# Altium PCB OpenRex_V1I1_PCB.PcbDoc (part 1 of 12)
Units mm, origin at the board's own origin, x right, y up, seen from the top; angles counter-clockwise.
Board outline 70 x 95 mm, 10 copper layers (L1, L2, L3, L4 (PWR), L5 (PWR), L6 (PWR), L7 (PWR), L8, L9, L10), stack 1.632 mm thick; 1080 components, 708 nets, 3831 pads, 2373 vias.
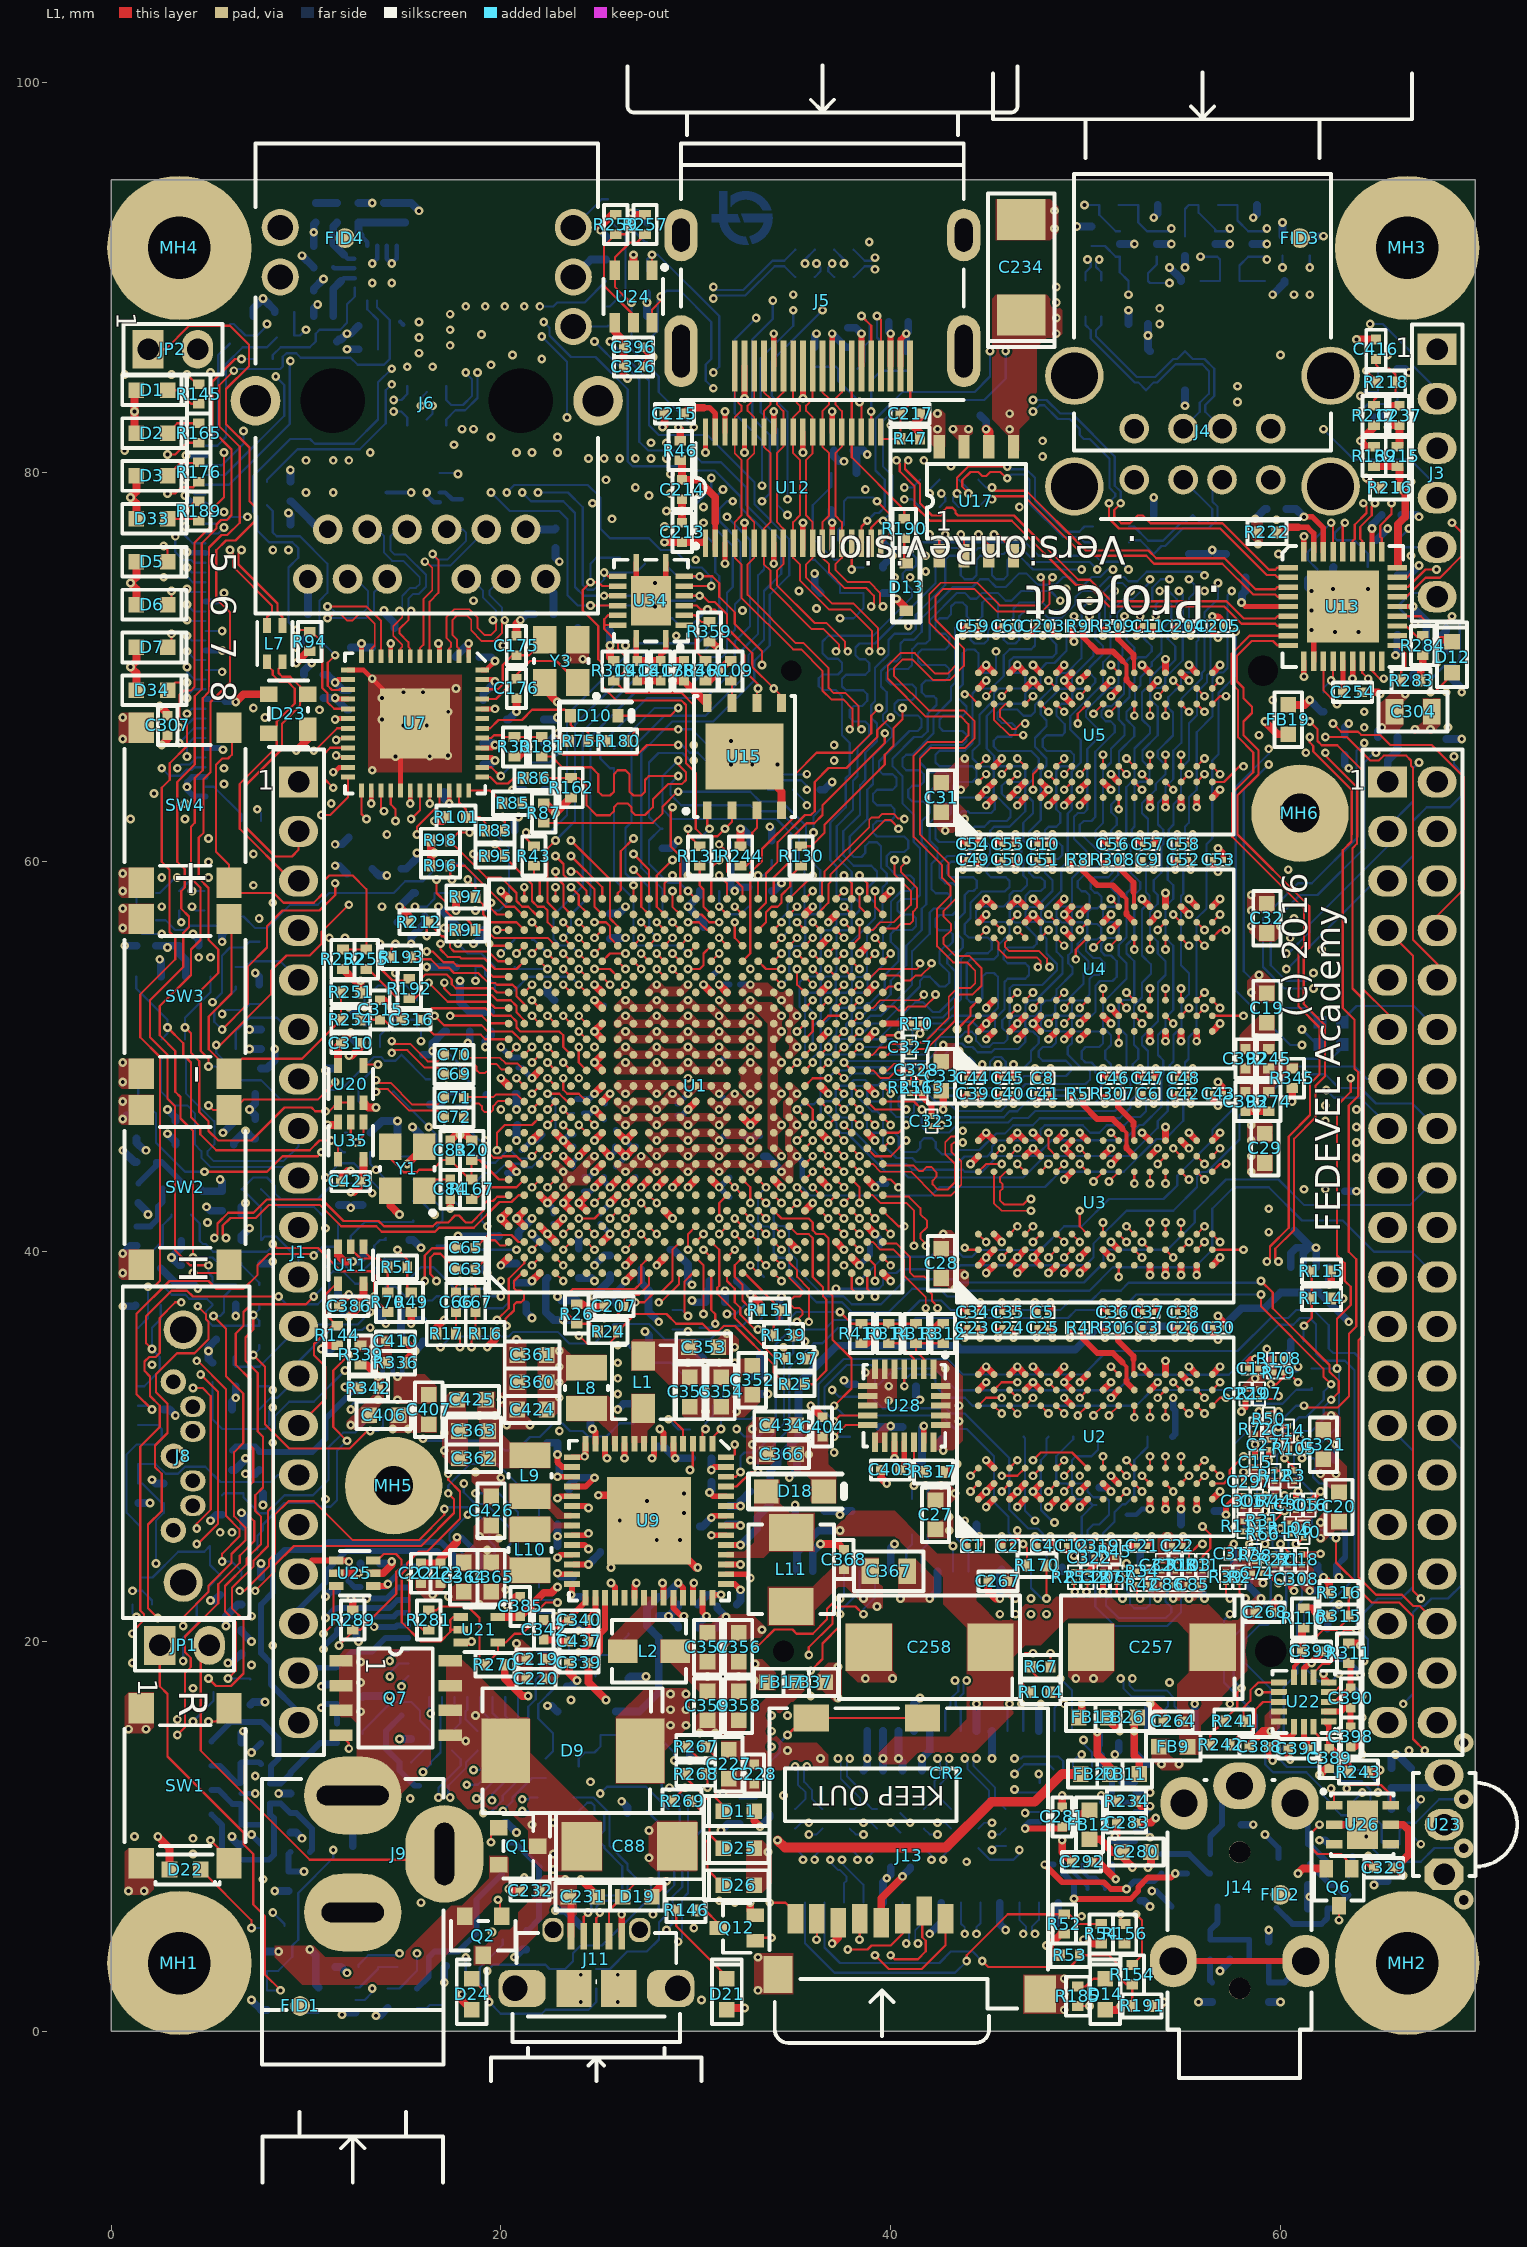
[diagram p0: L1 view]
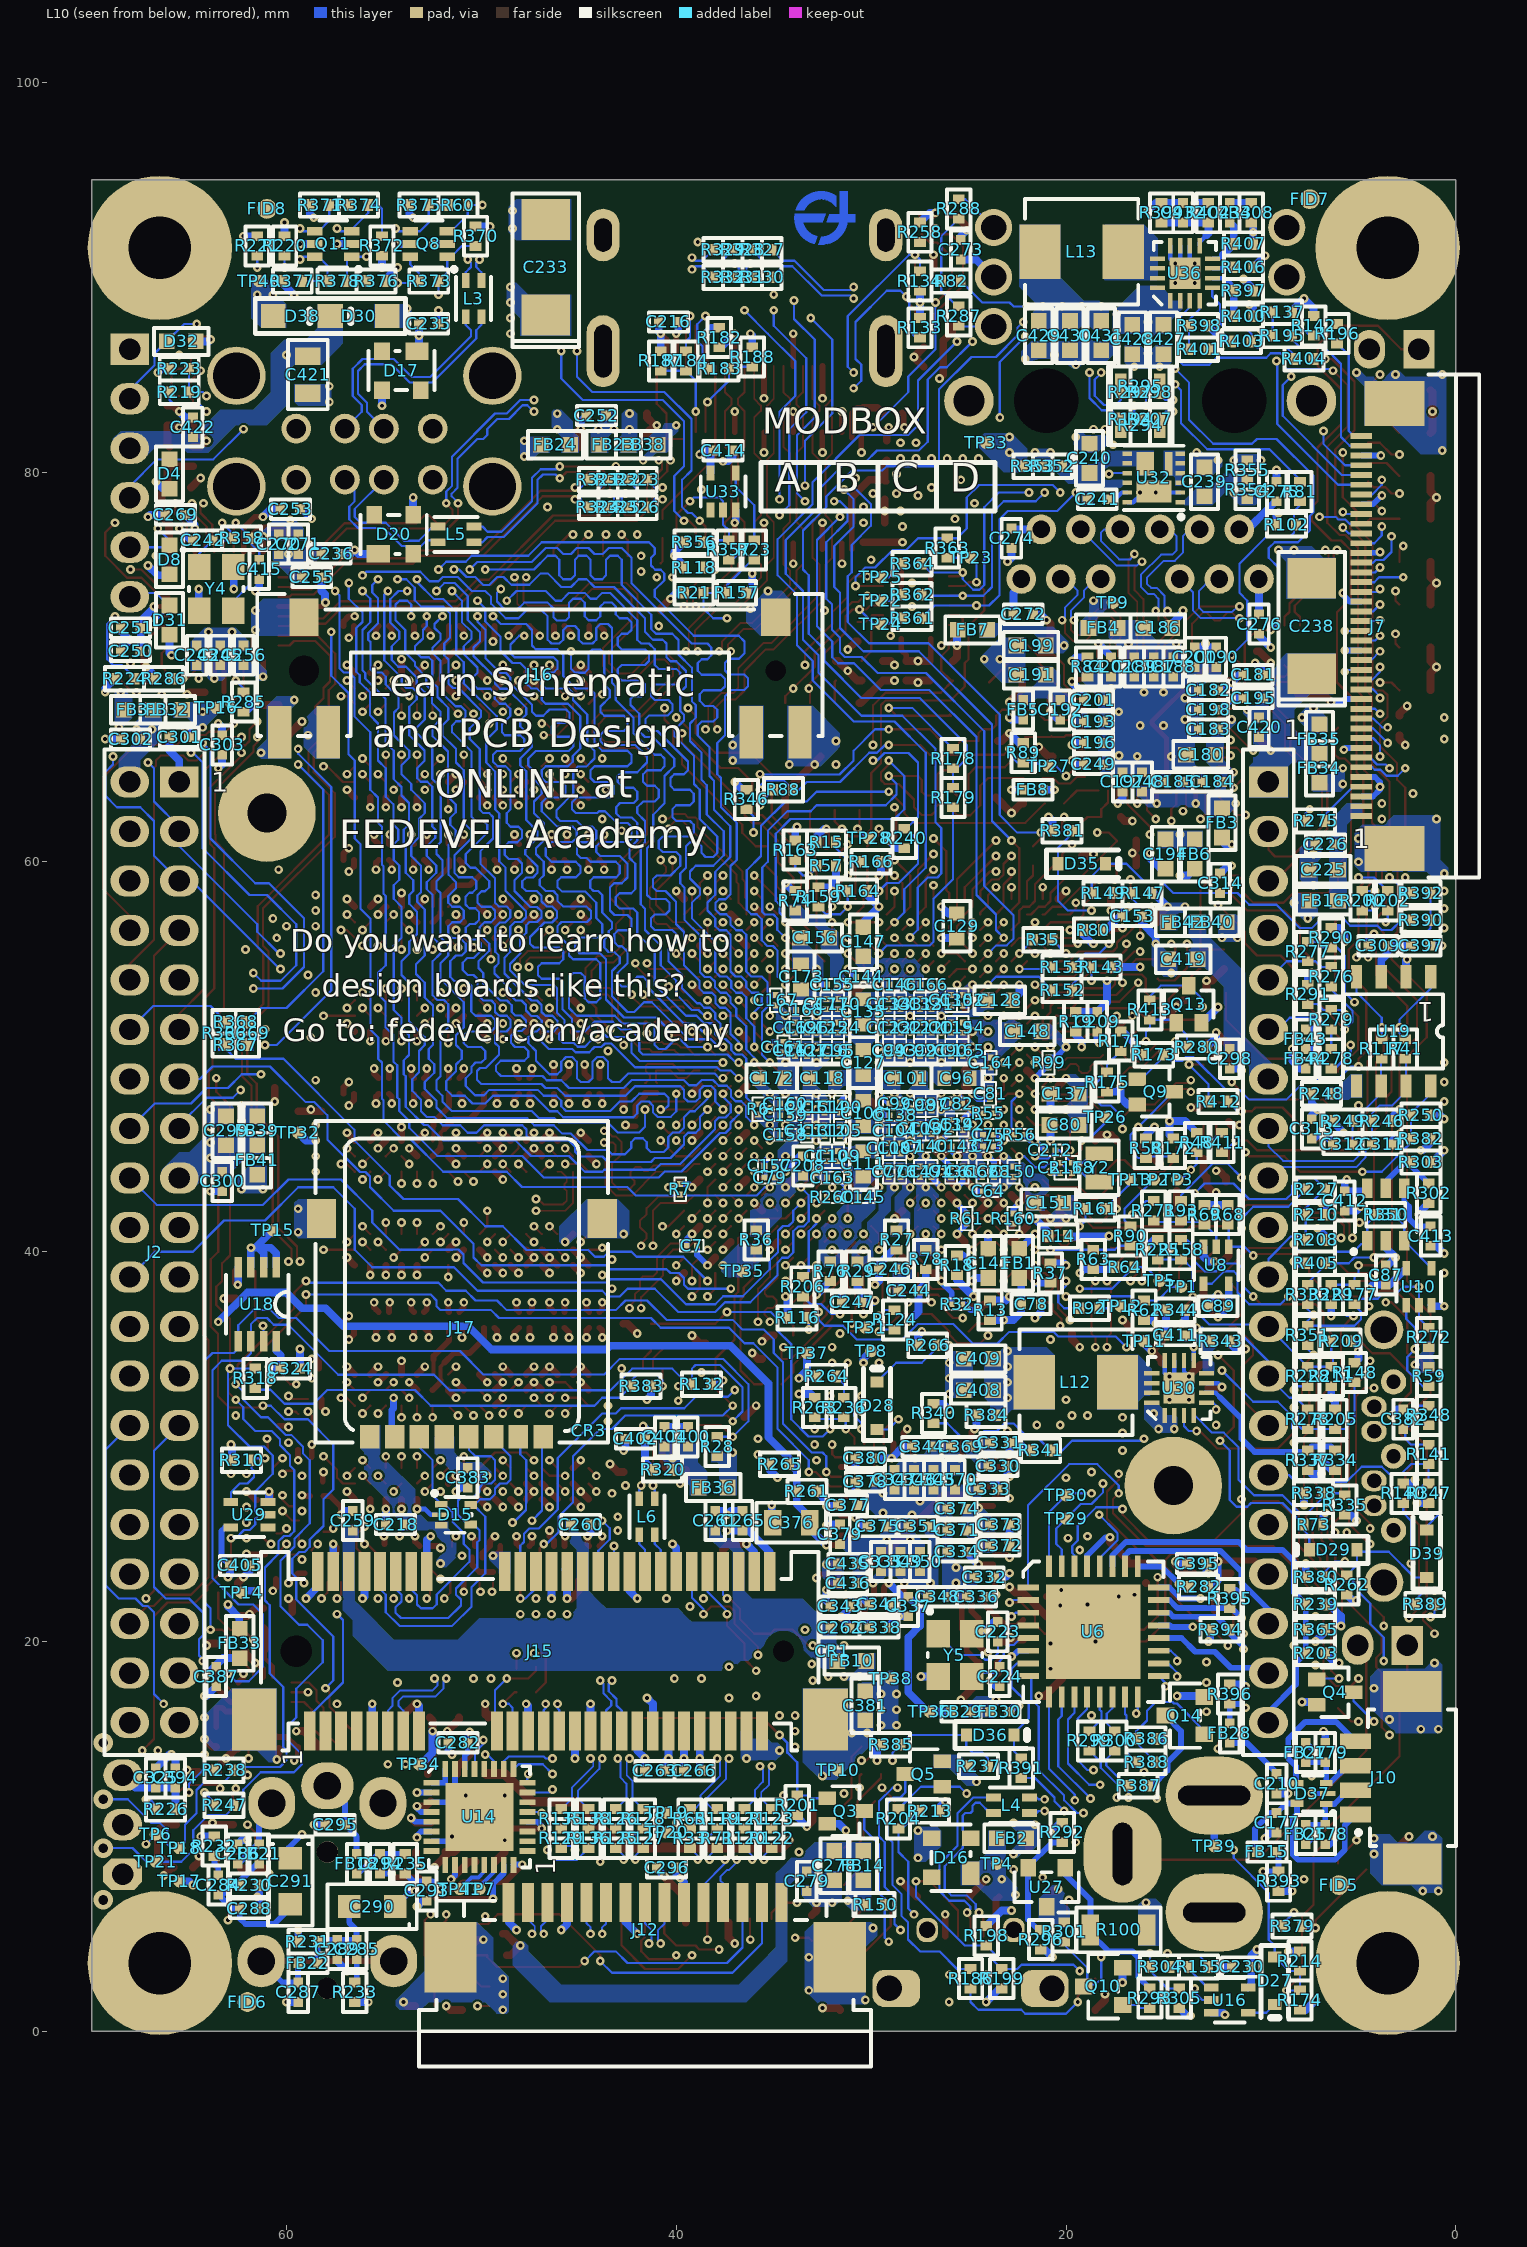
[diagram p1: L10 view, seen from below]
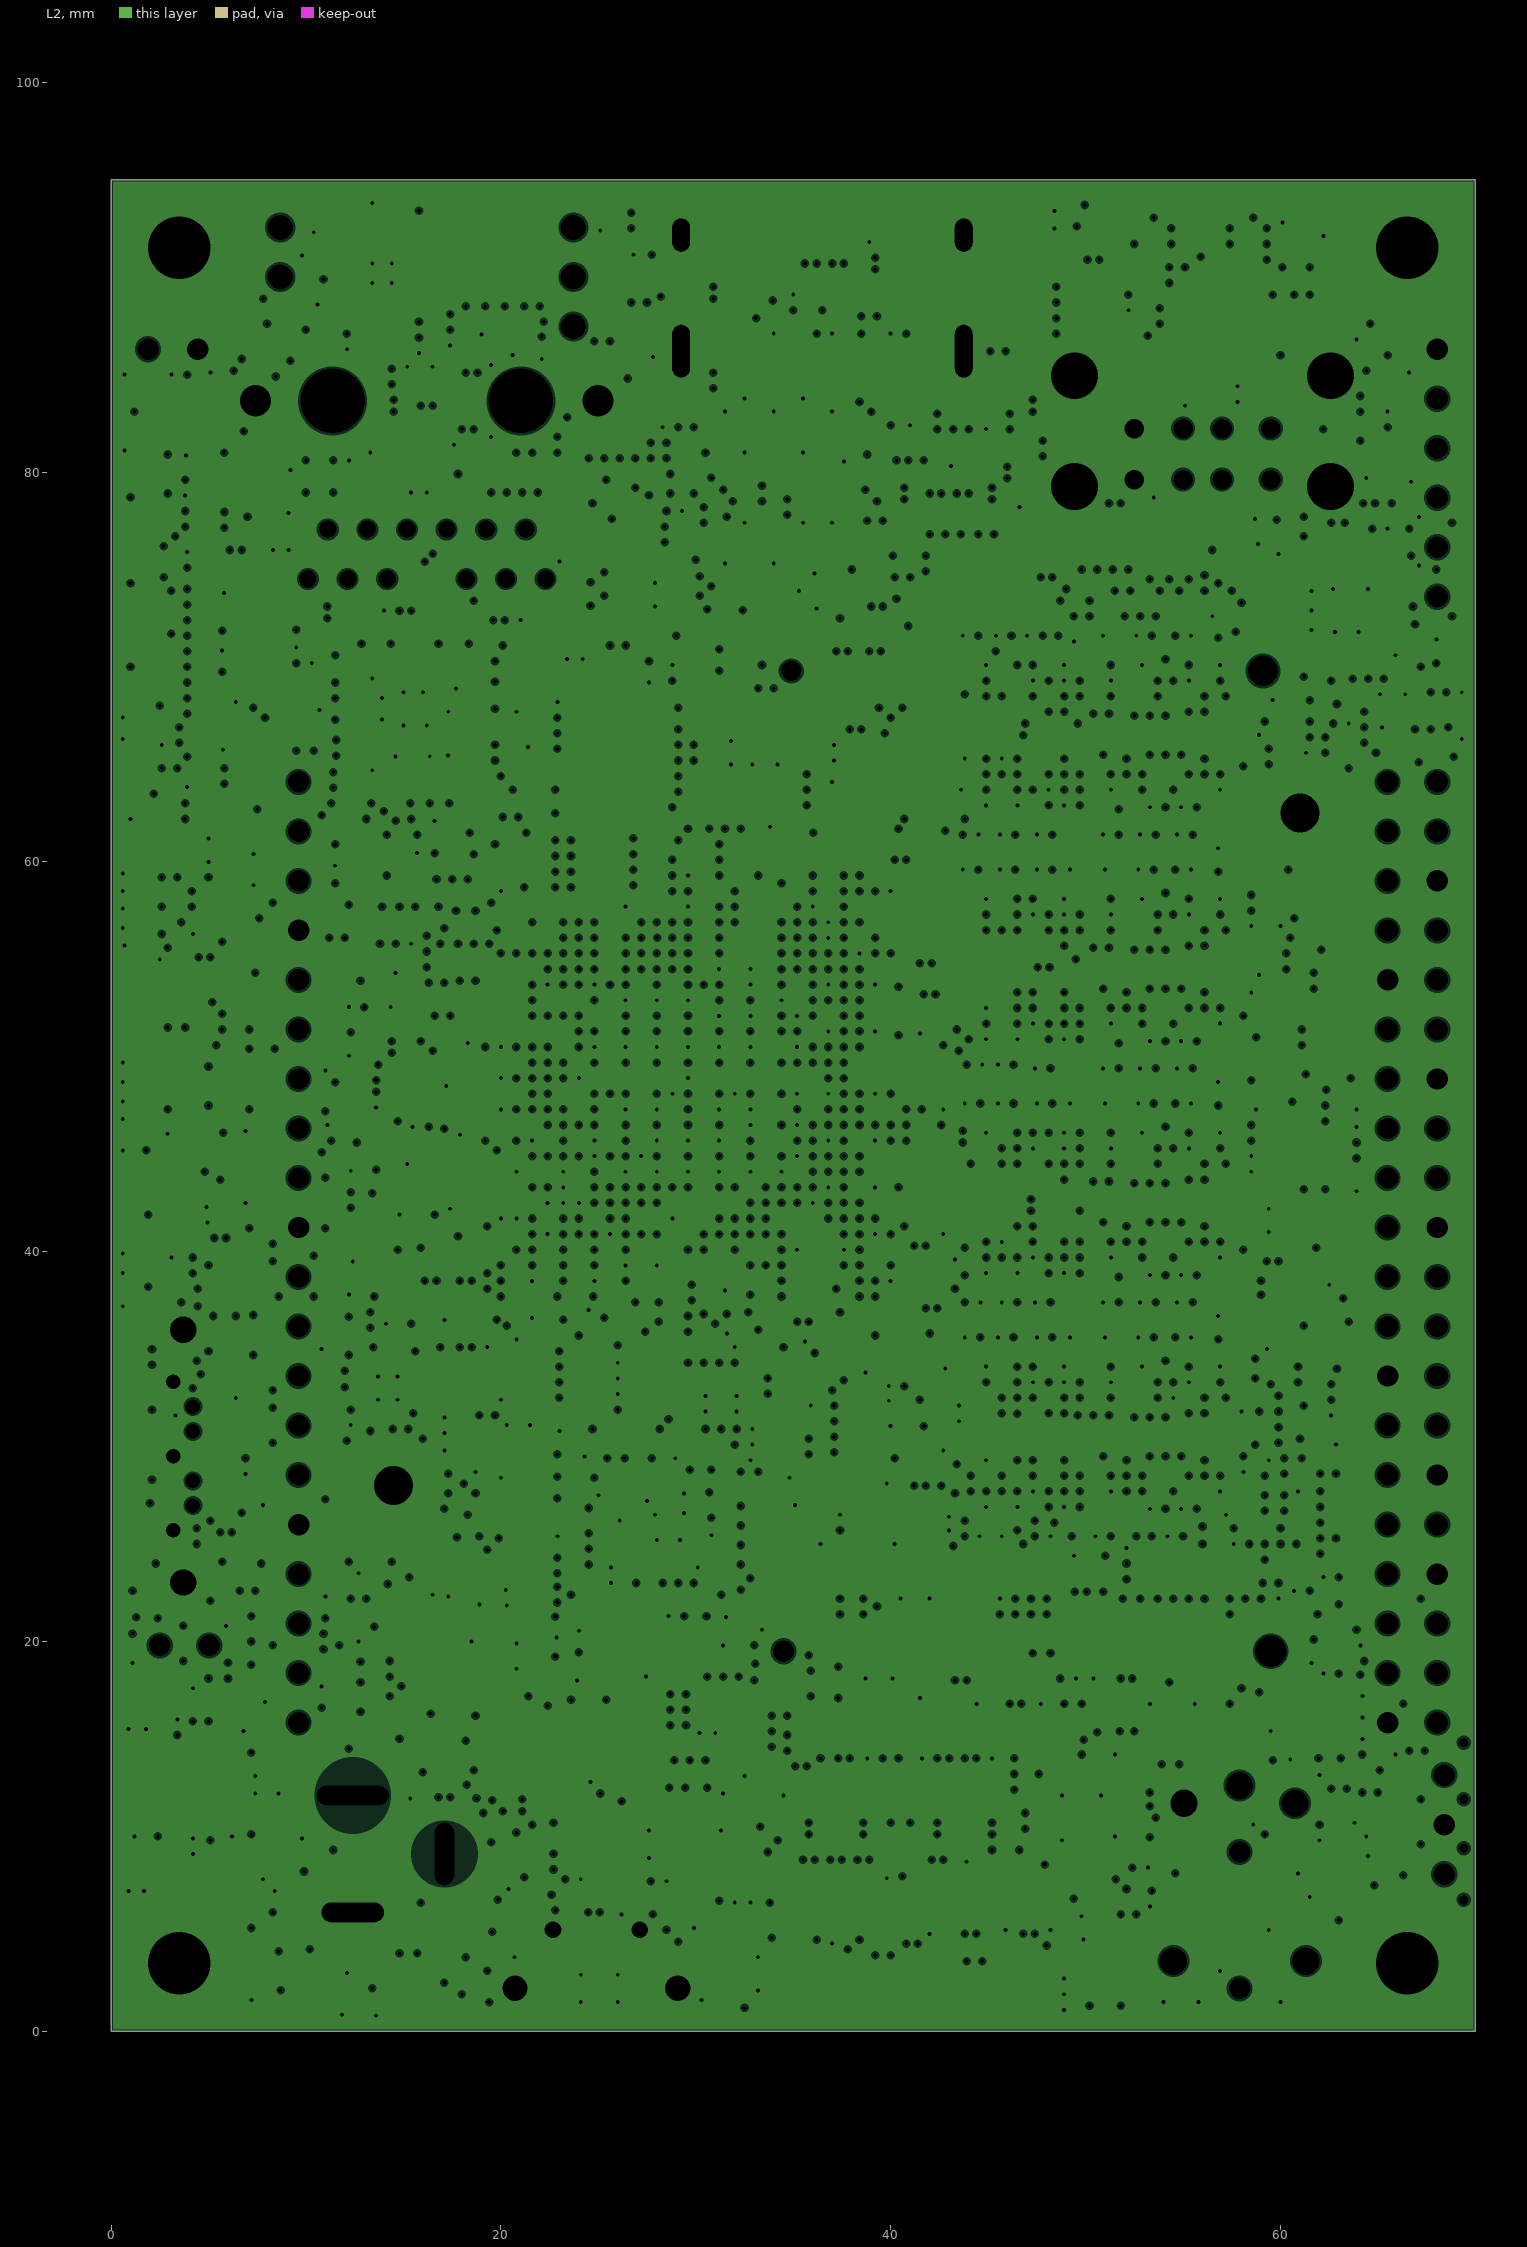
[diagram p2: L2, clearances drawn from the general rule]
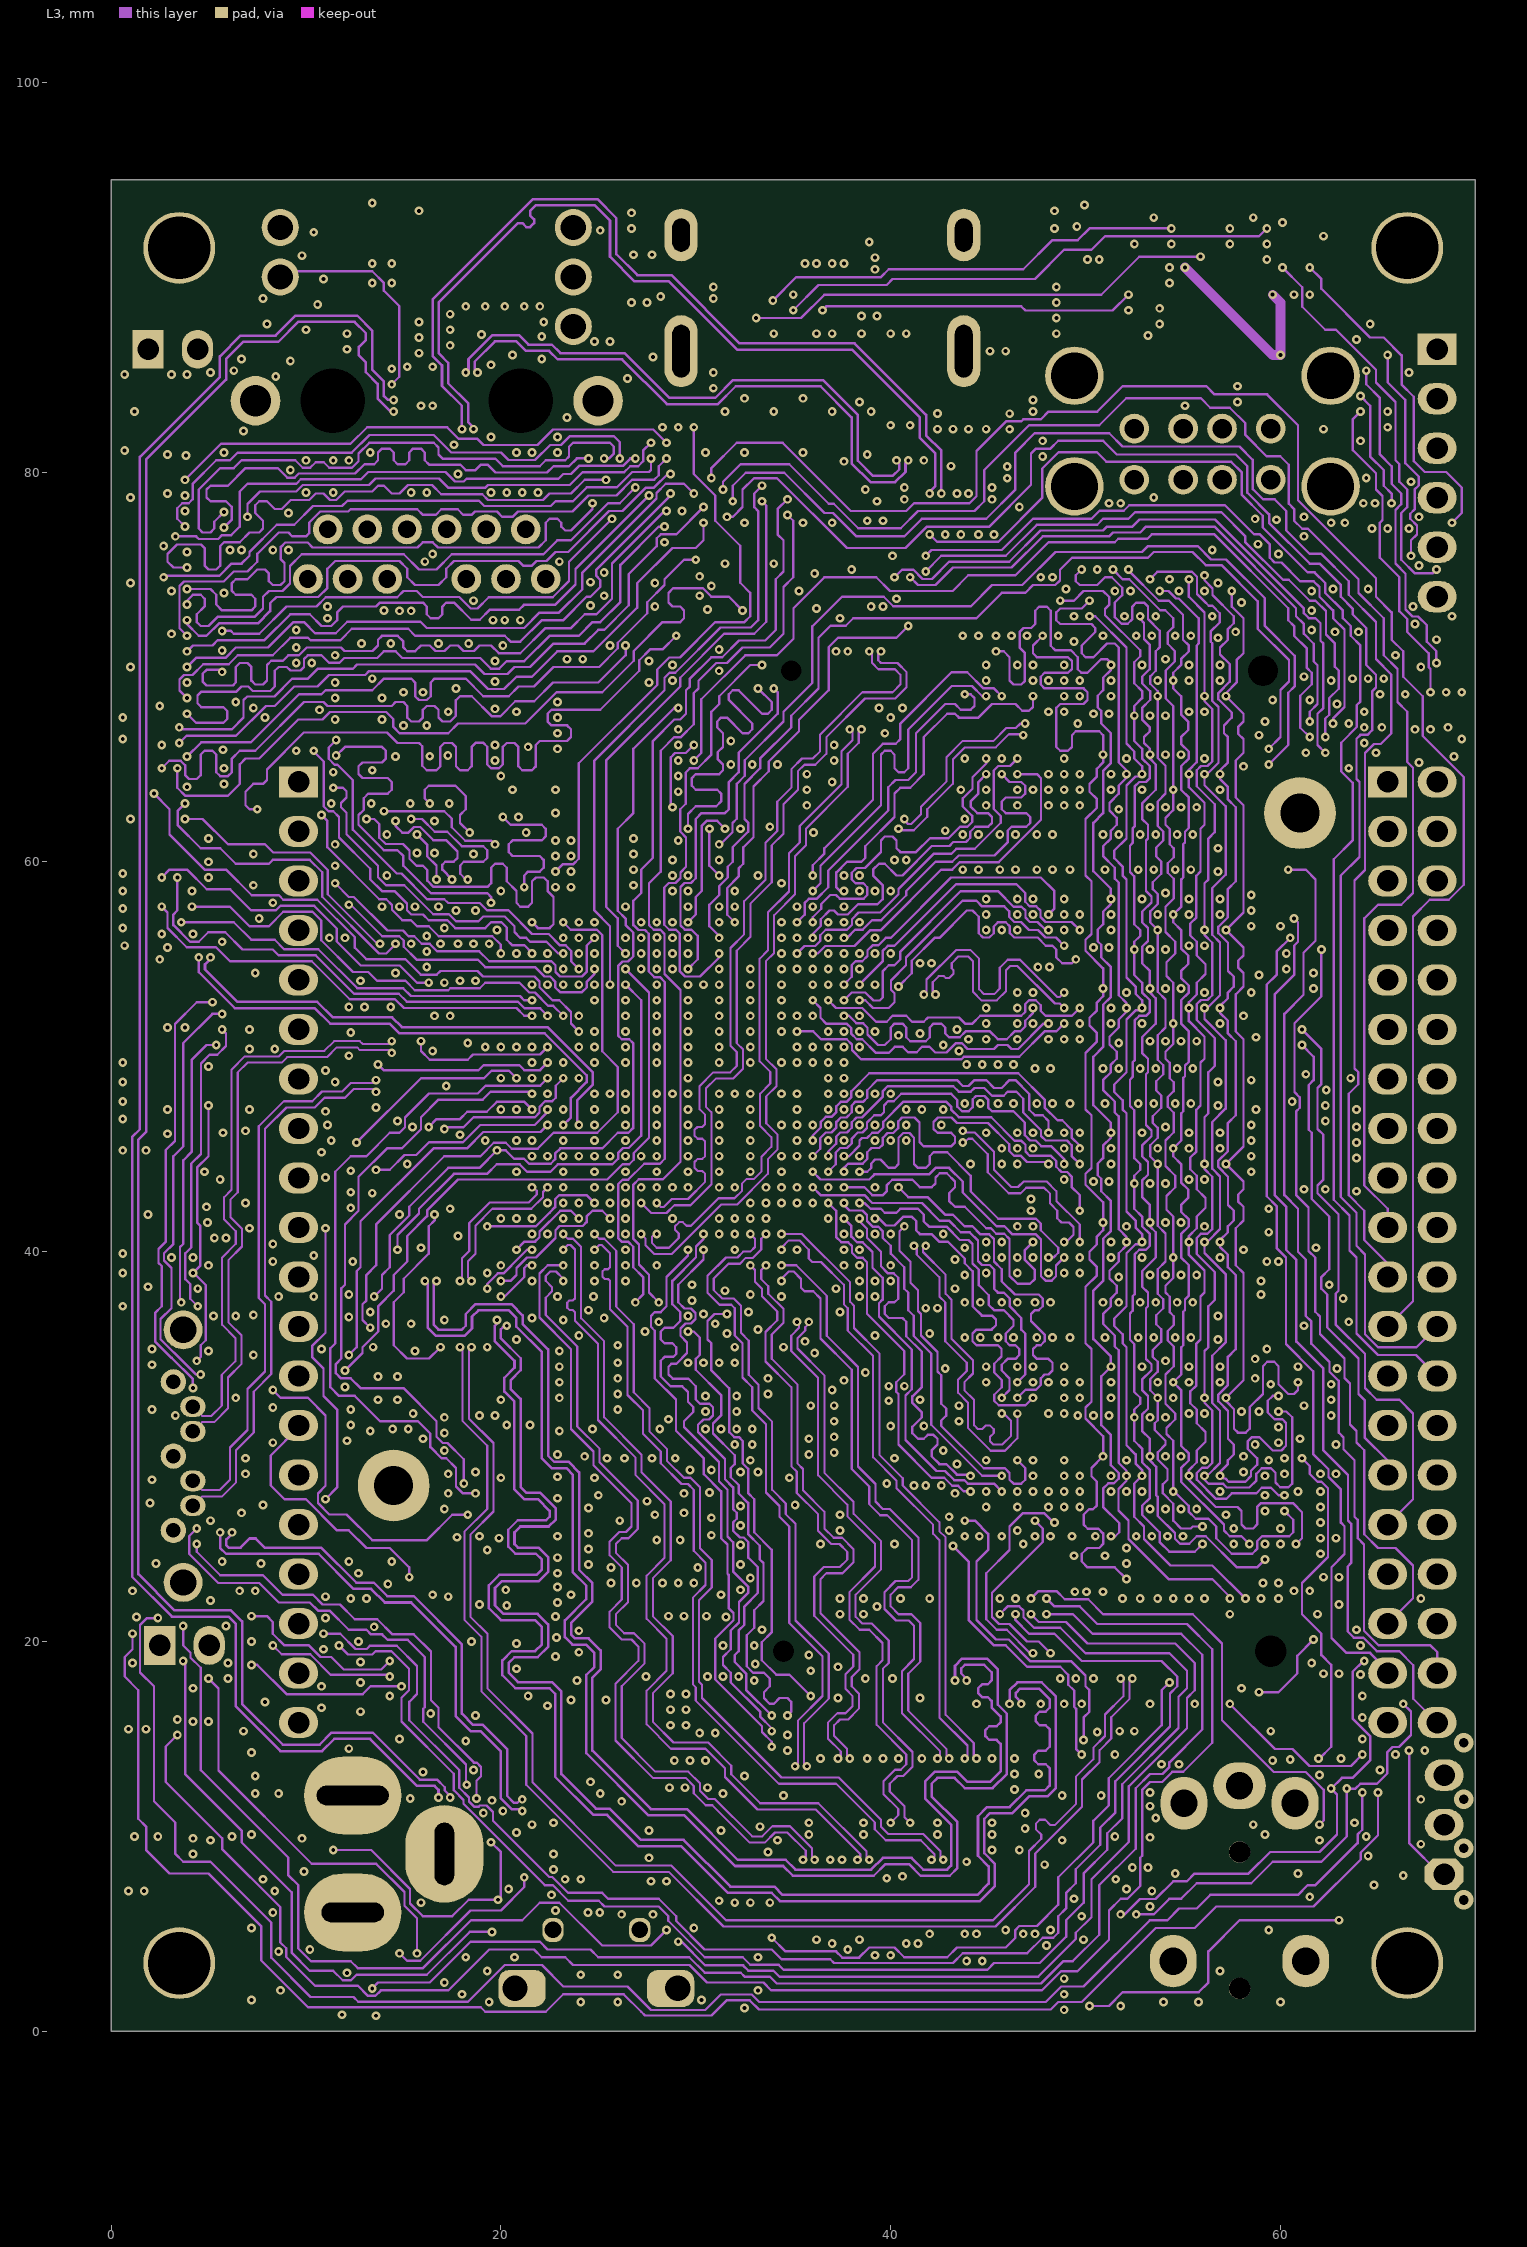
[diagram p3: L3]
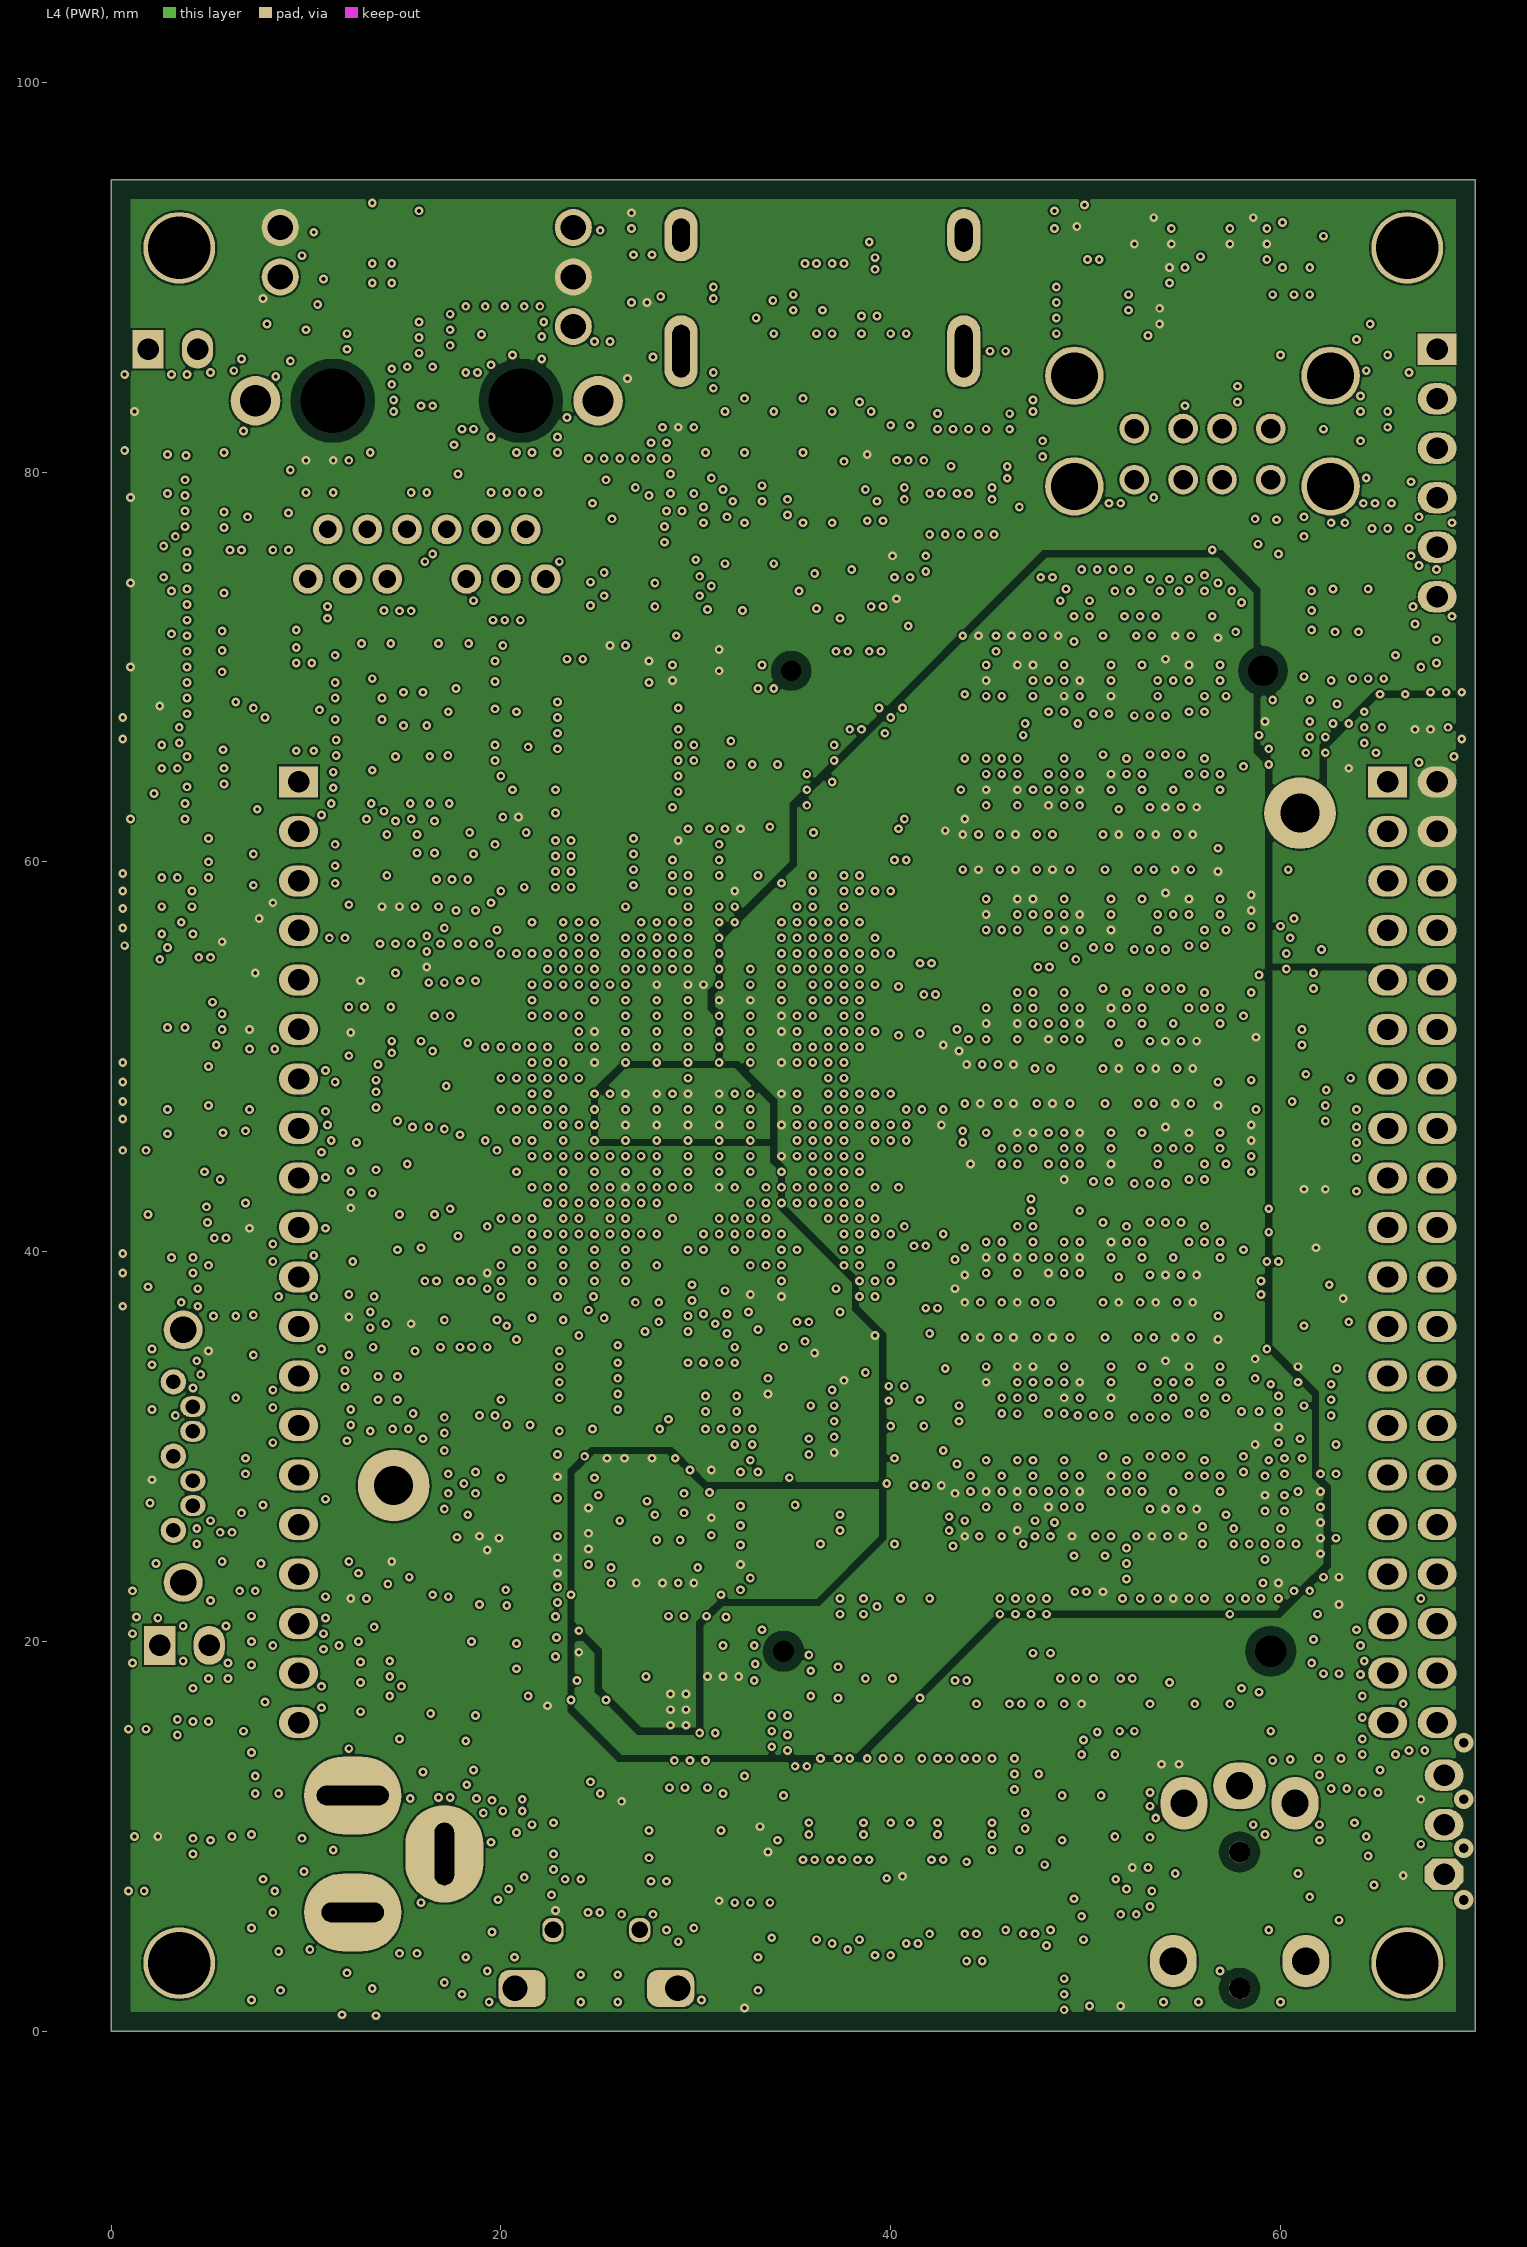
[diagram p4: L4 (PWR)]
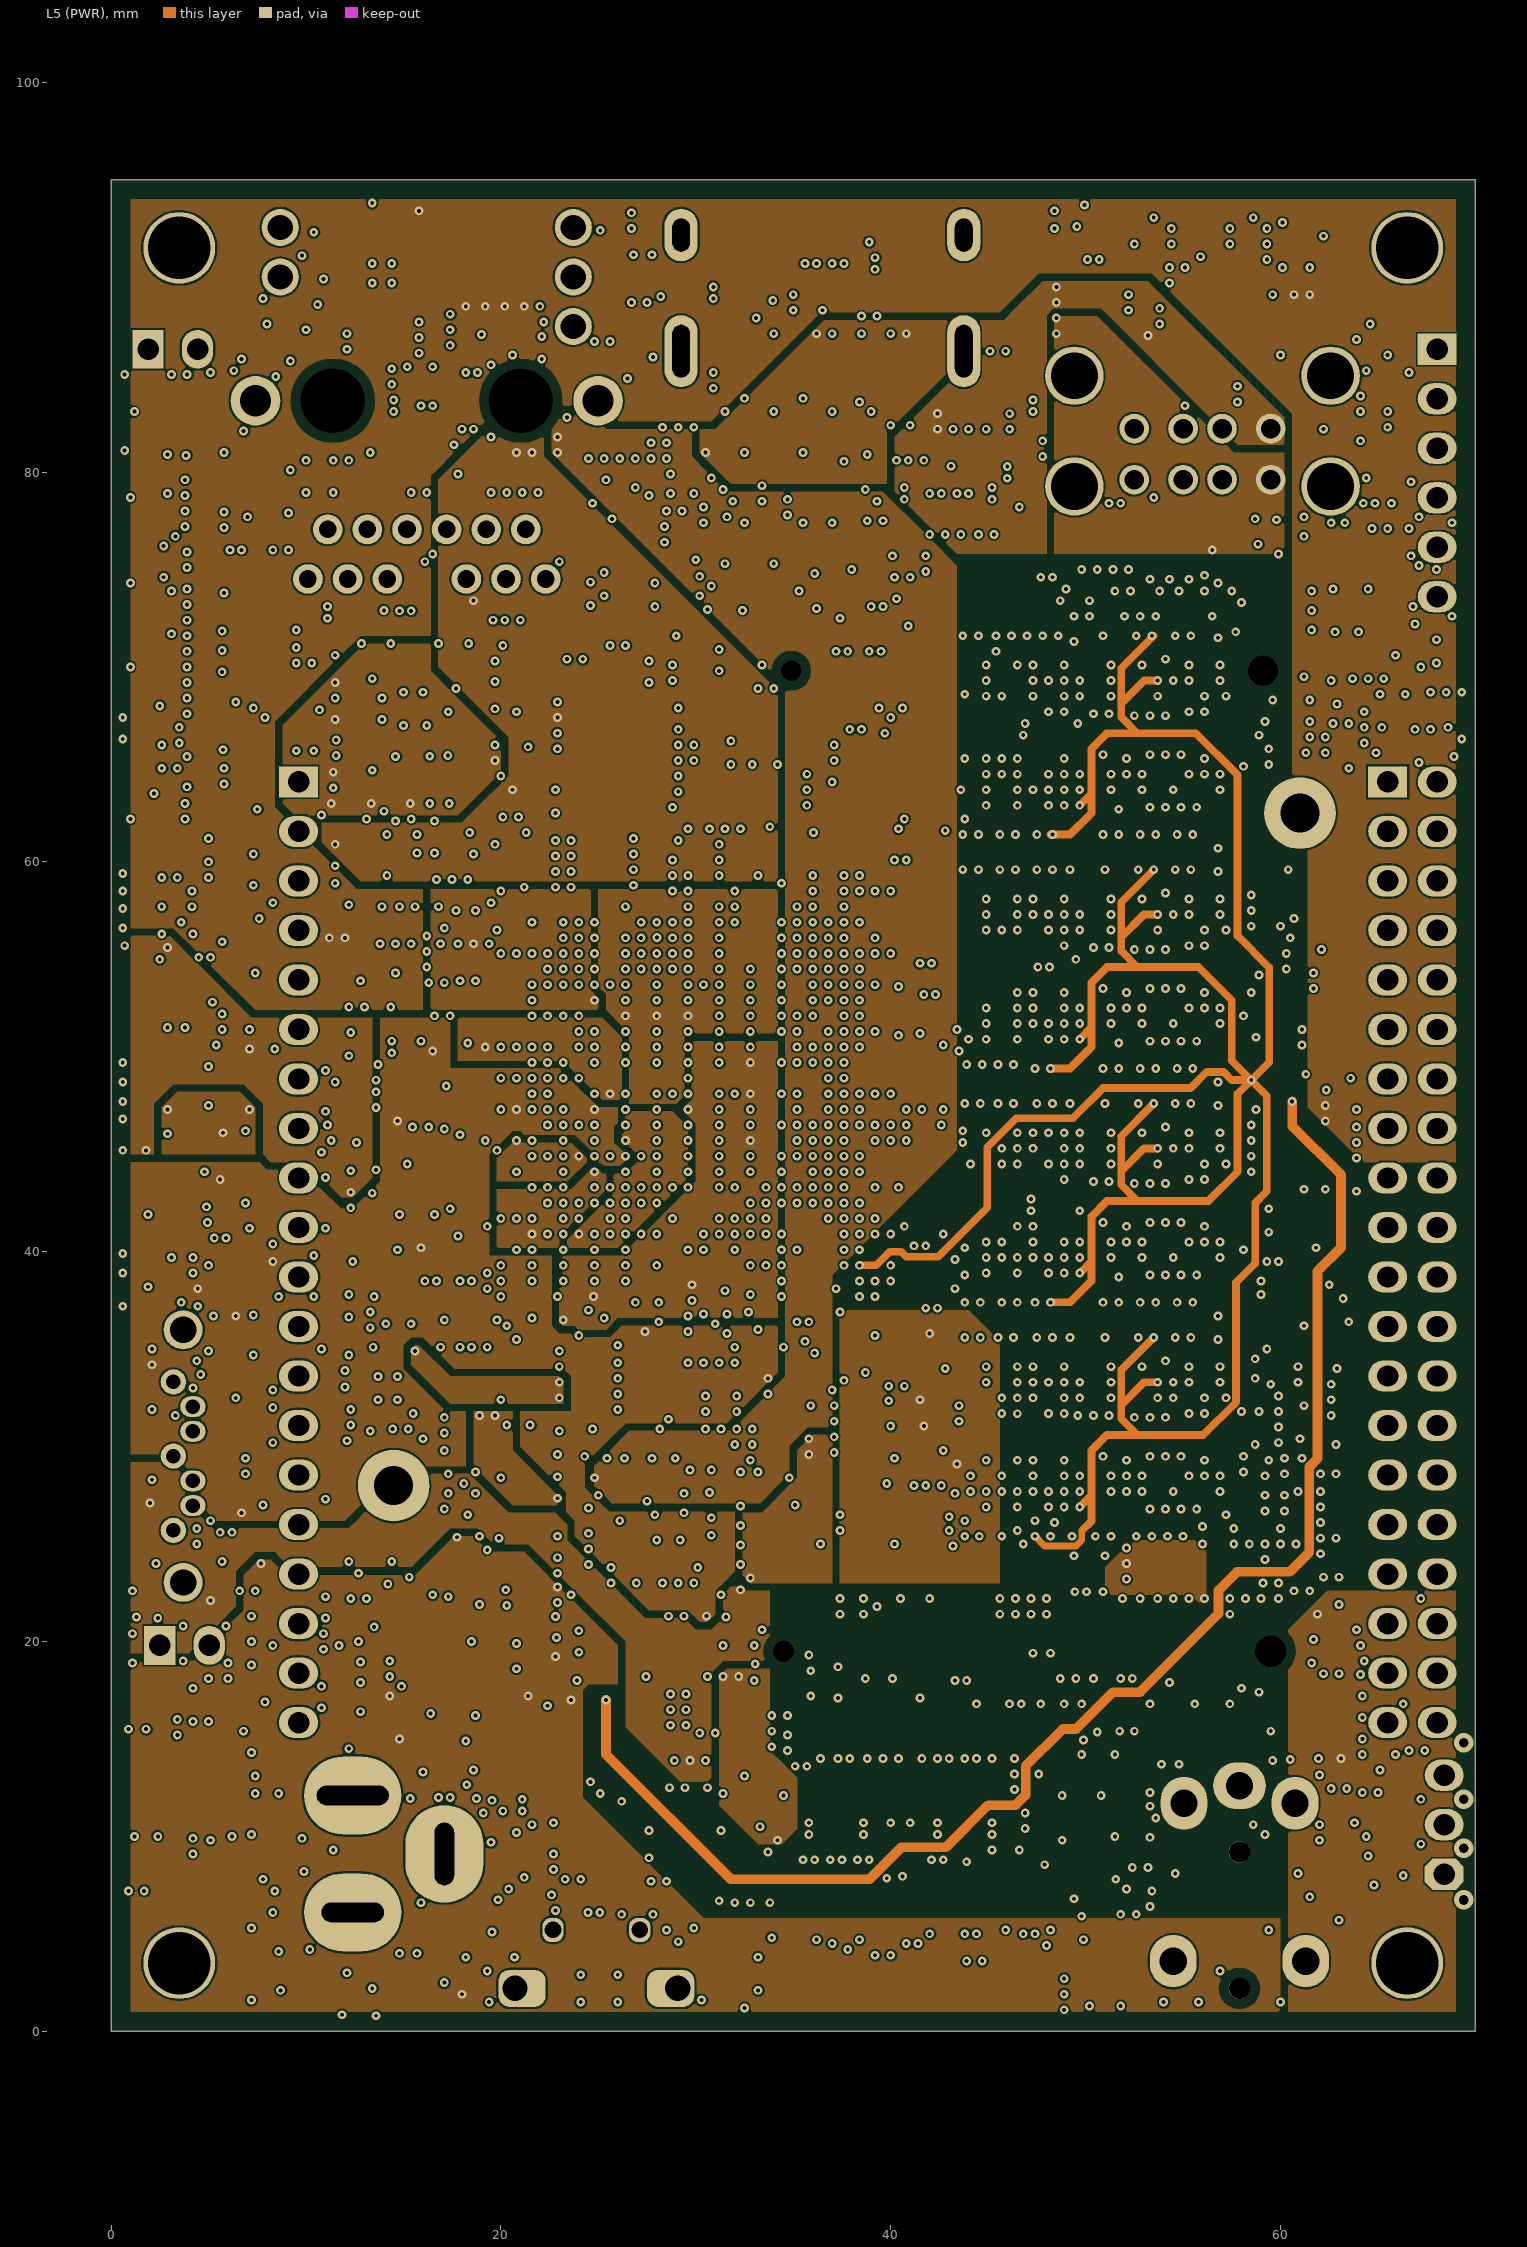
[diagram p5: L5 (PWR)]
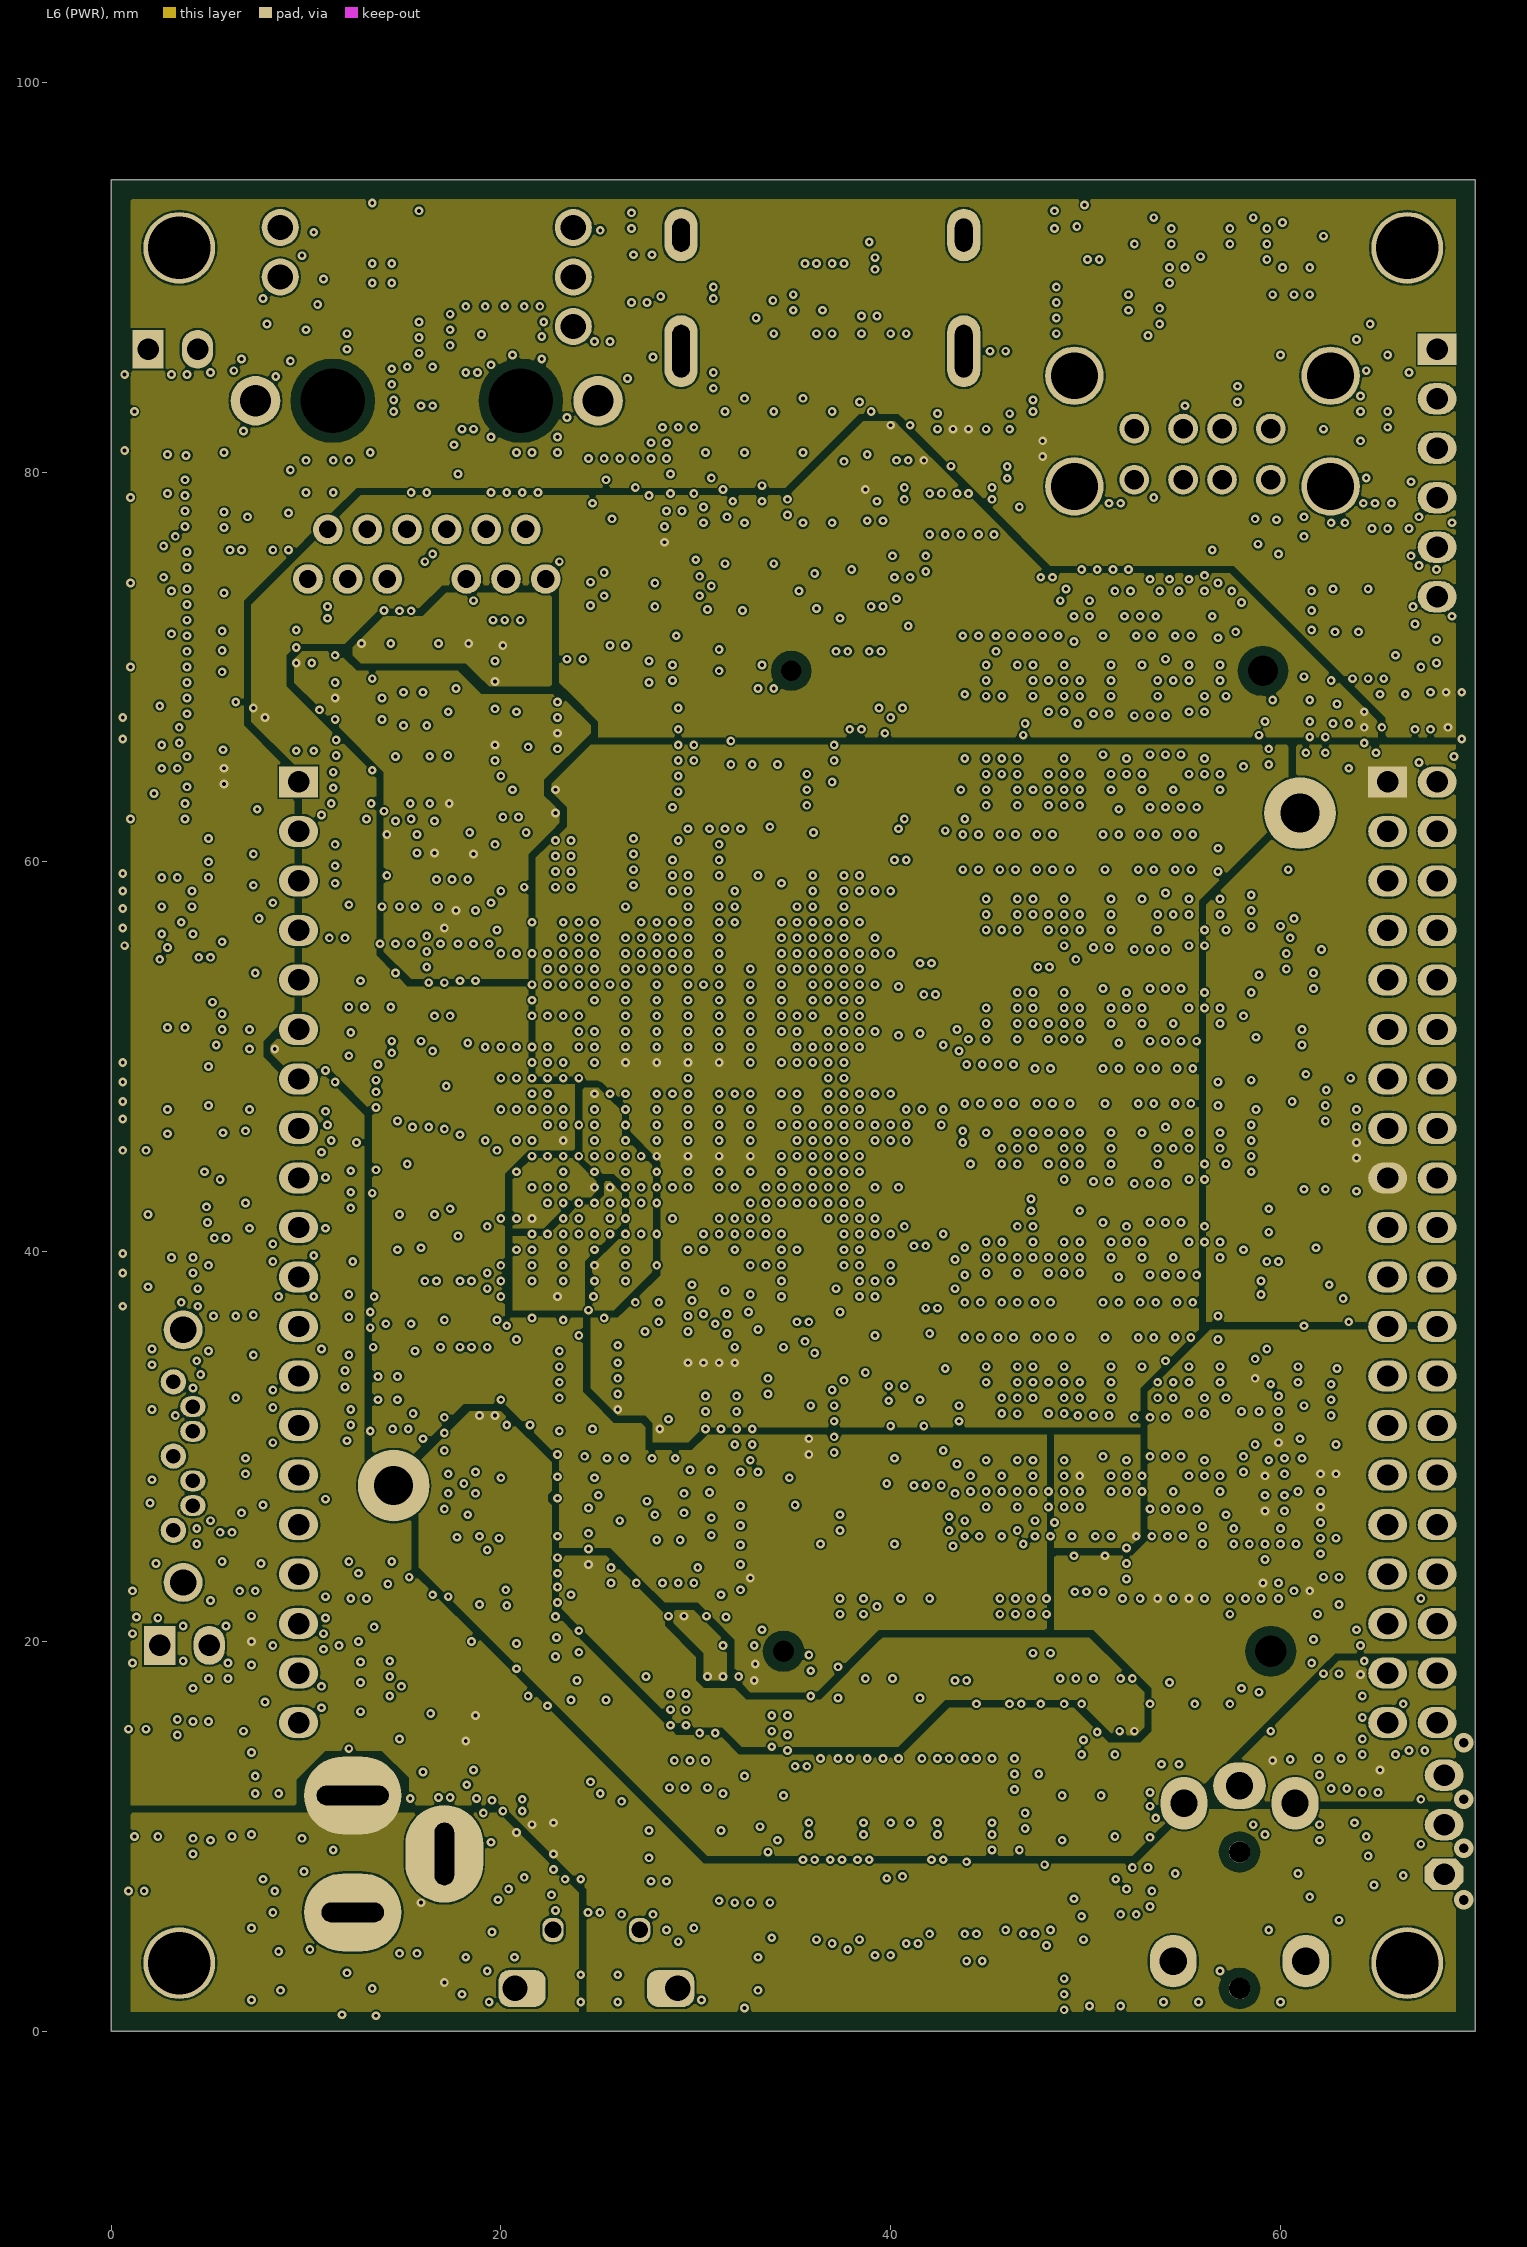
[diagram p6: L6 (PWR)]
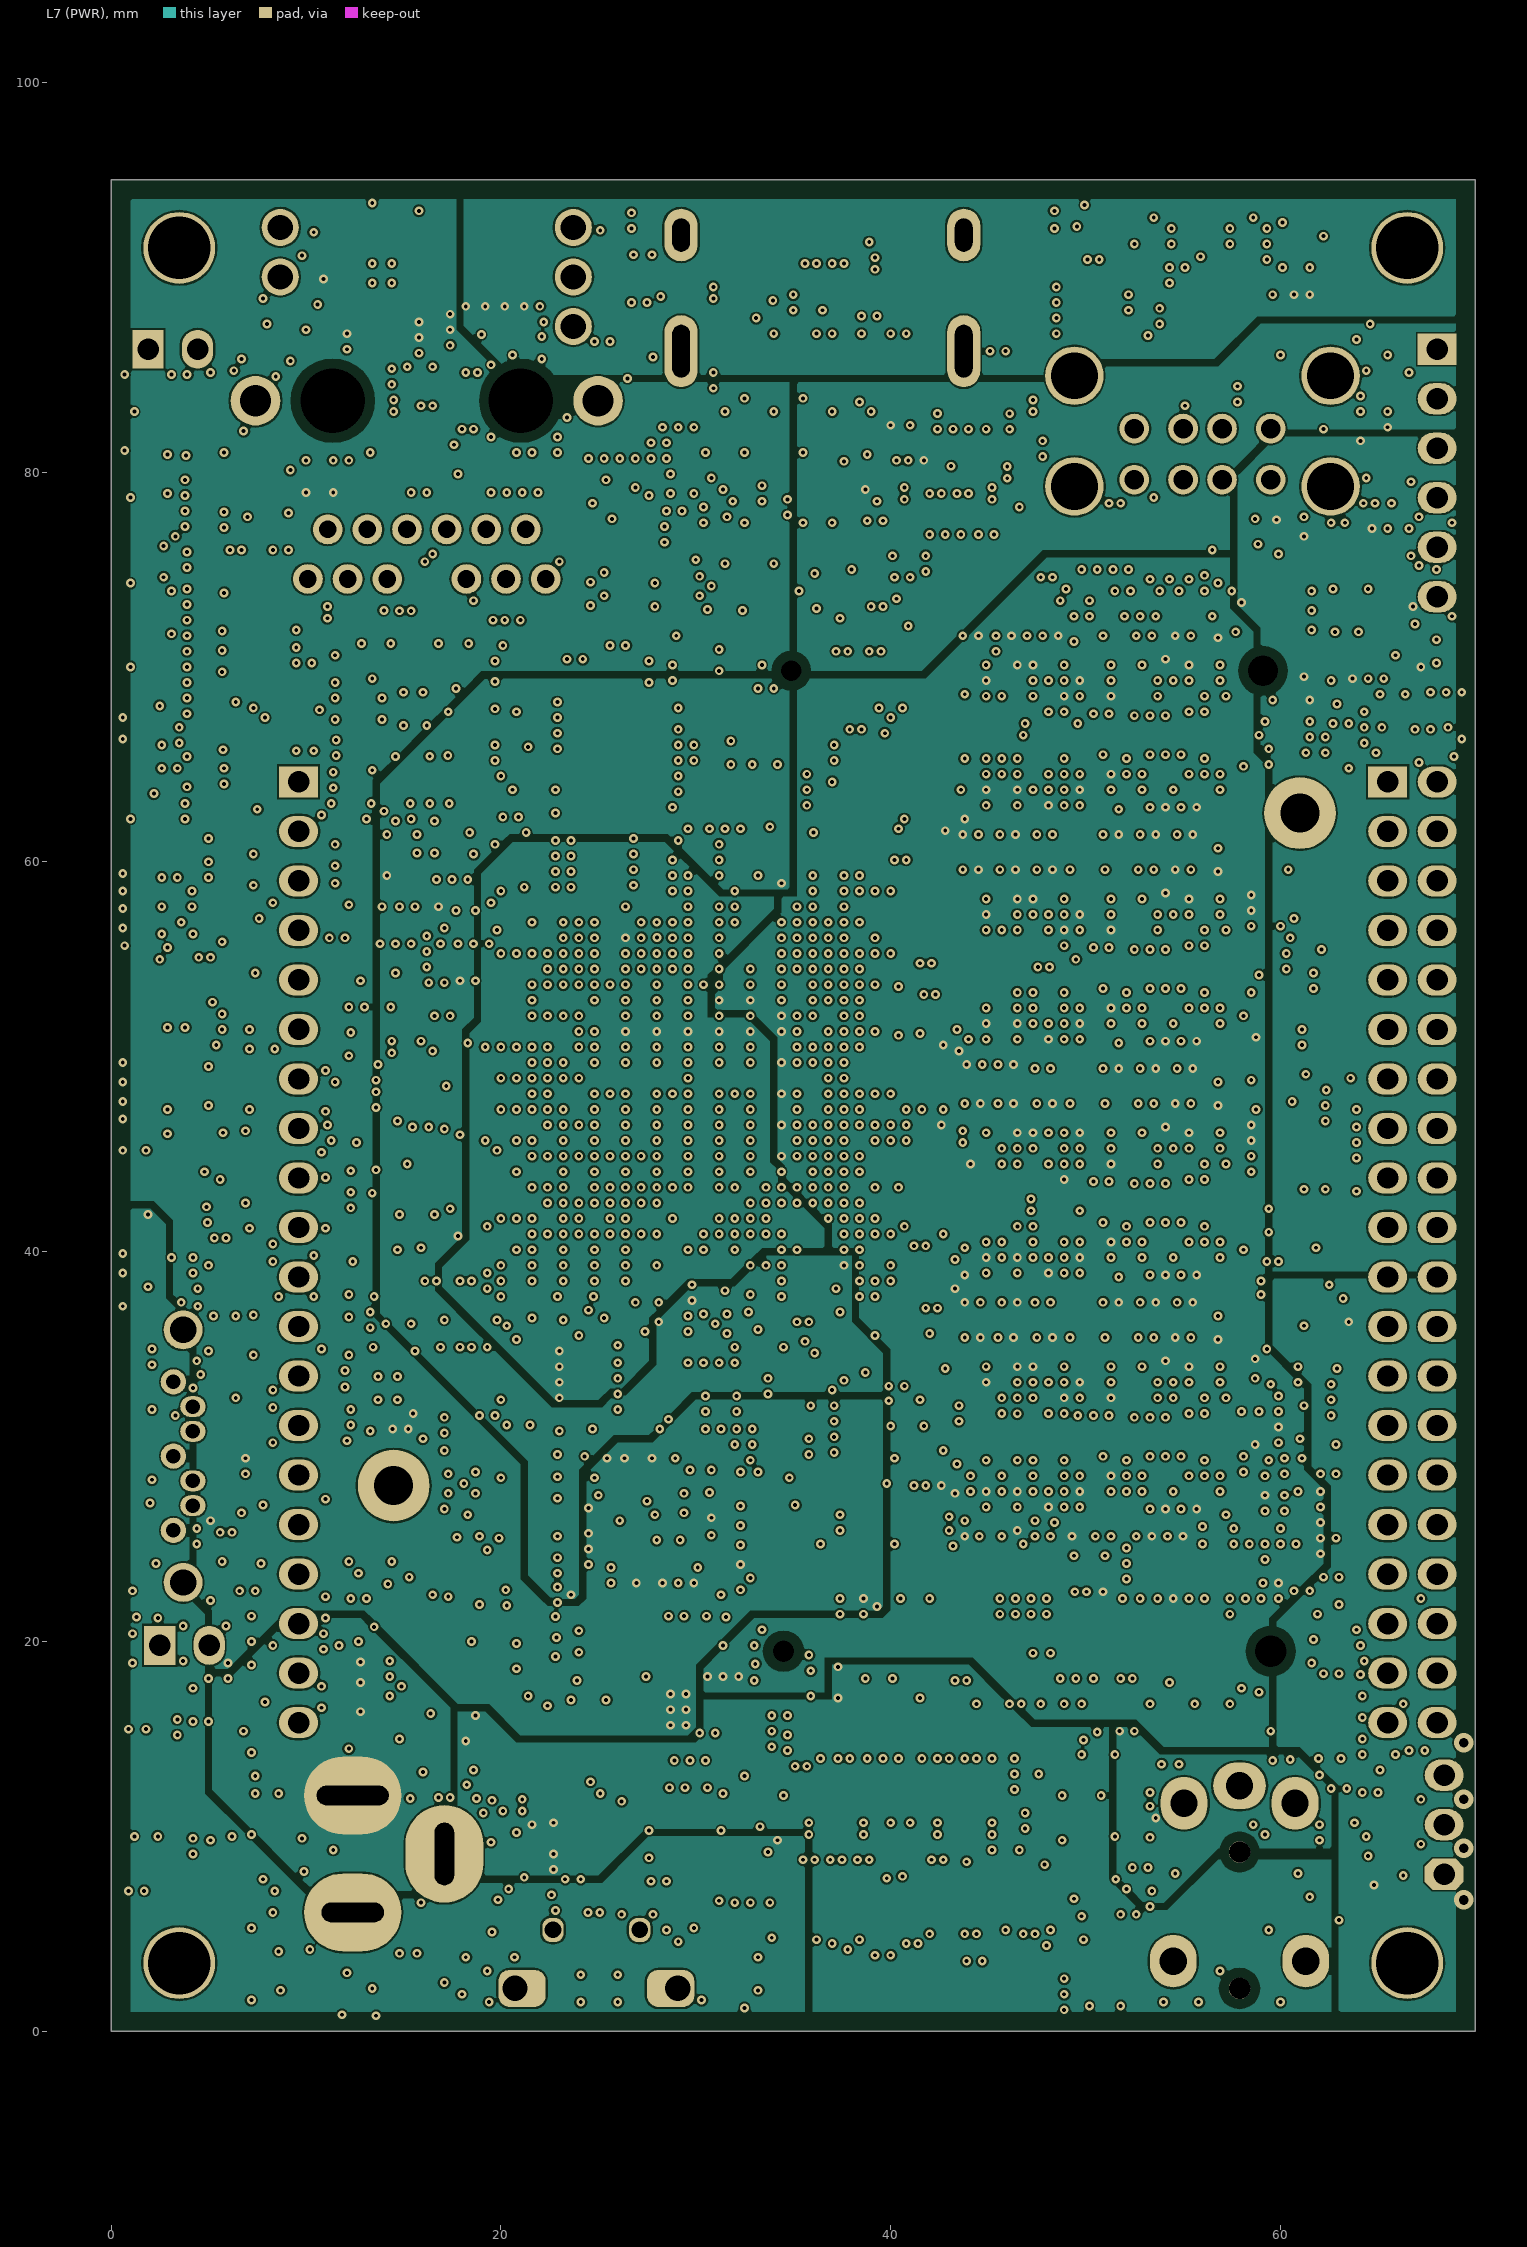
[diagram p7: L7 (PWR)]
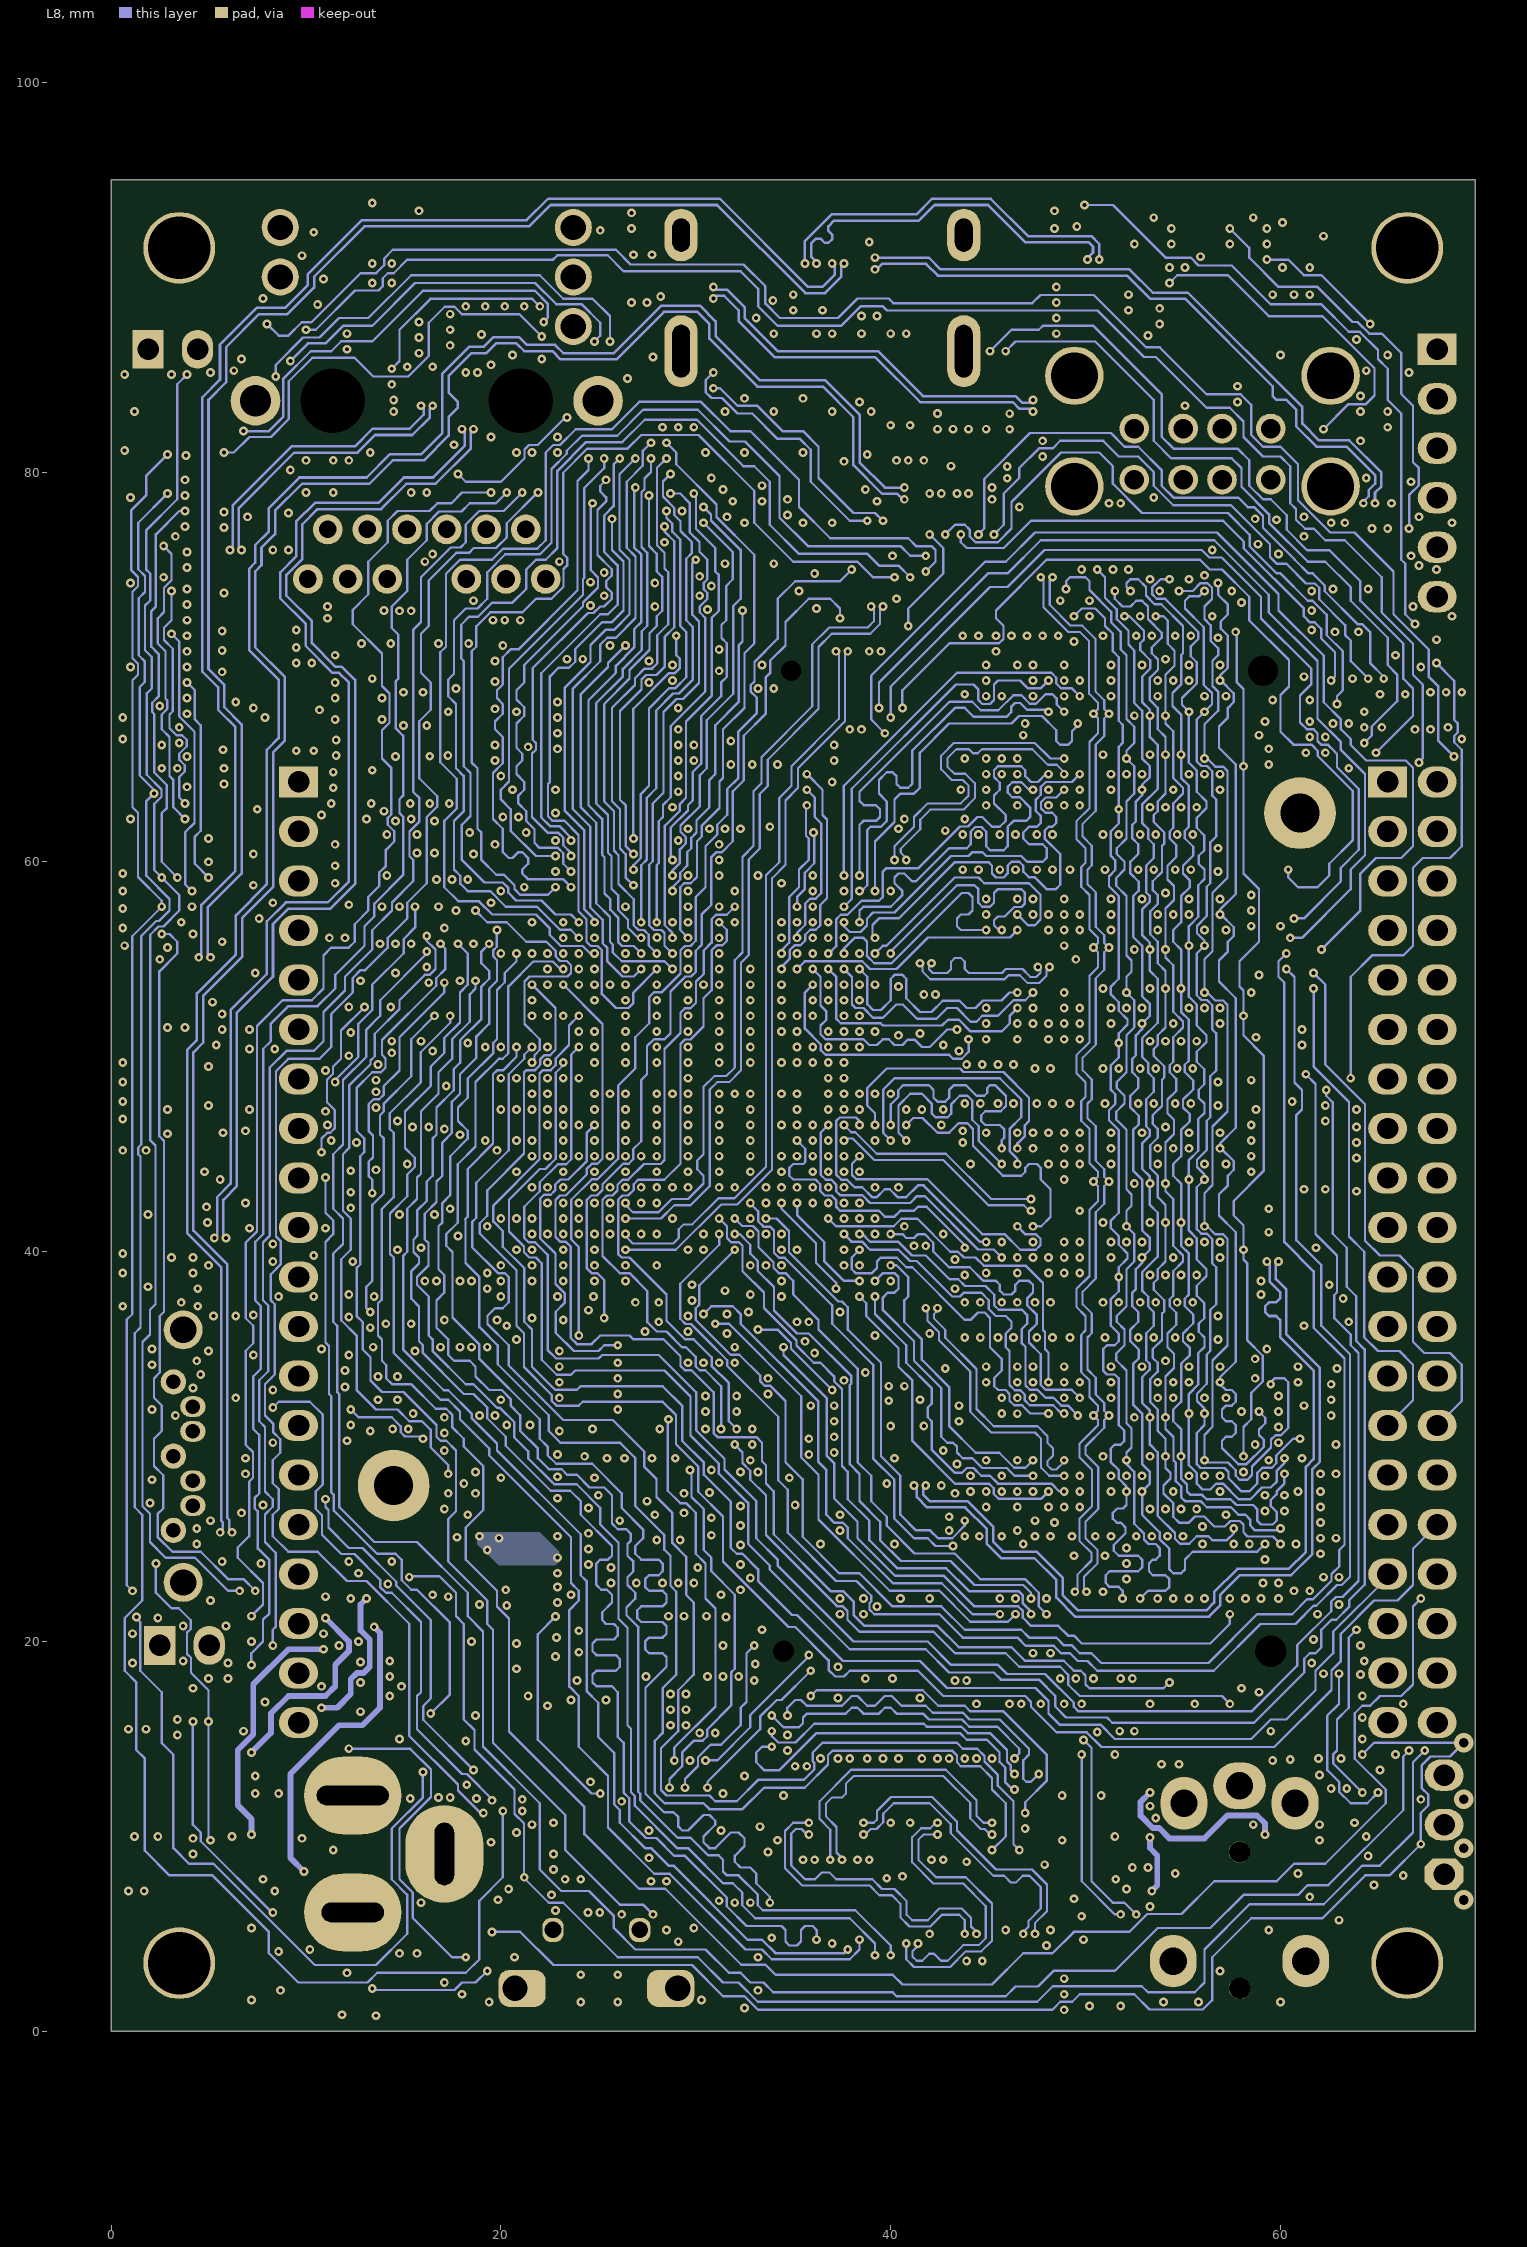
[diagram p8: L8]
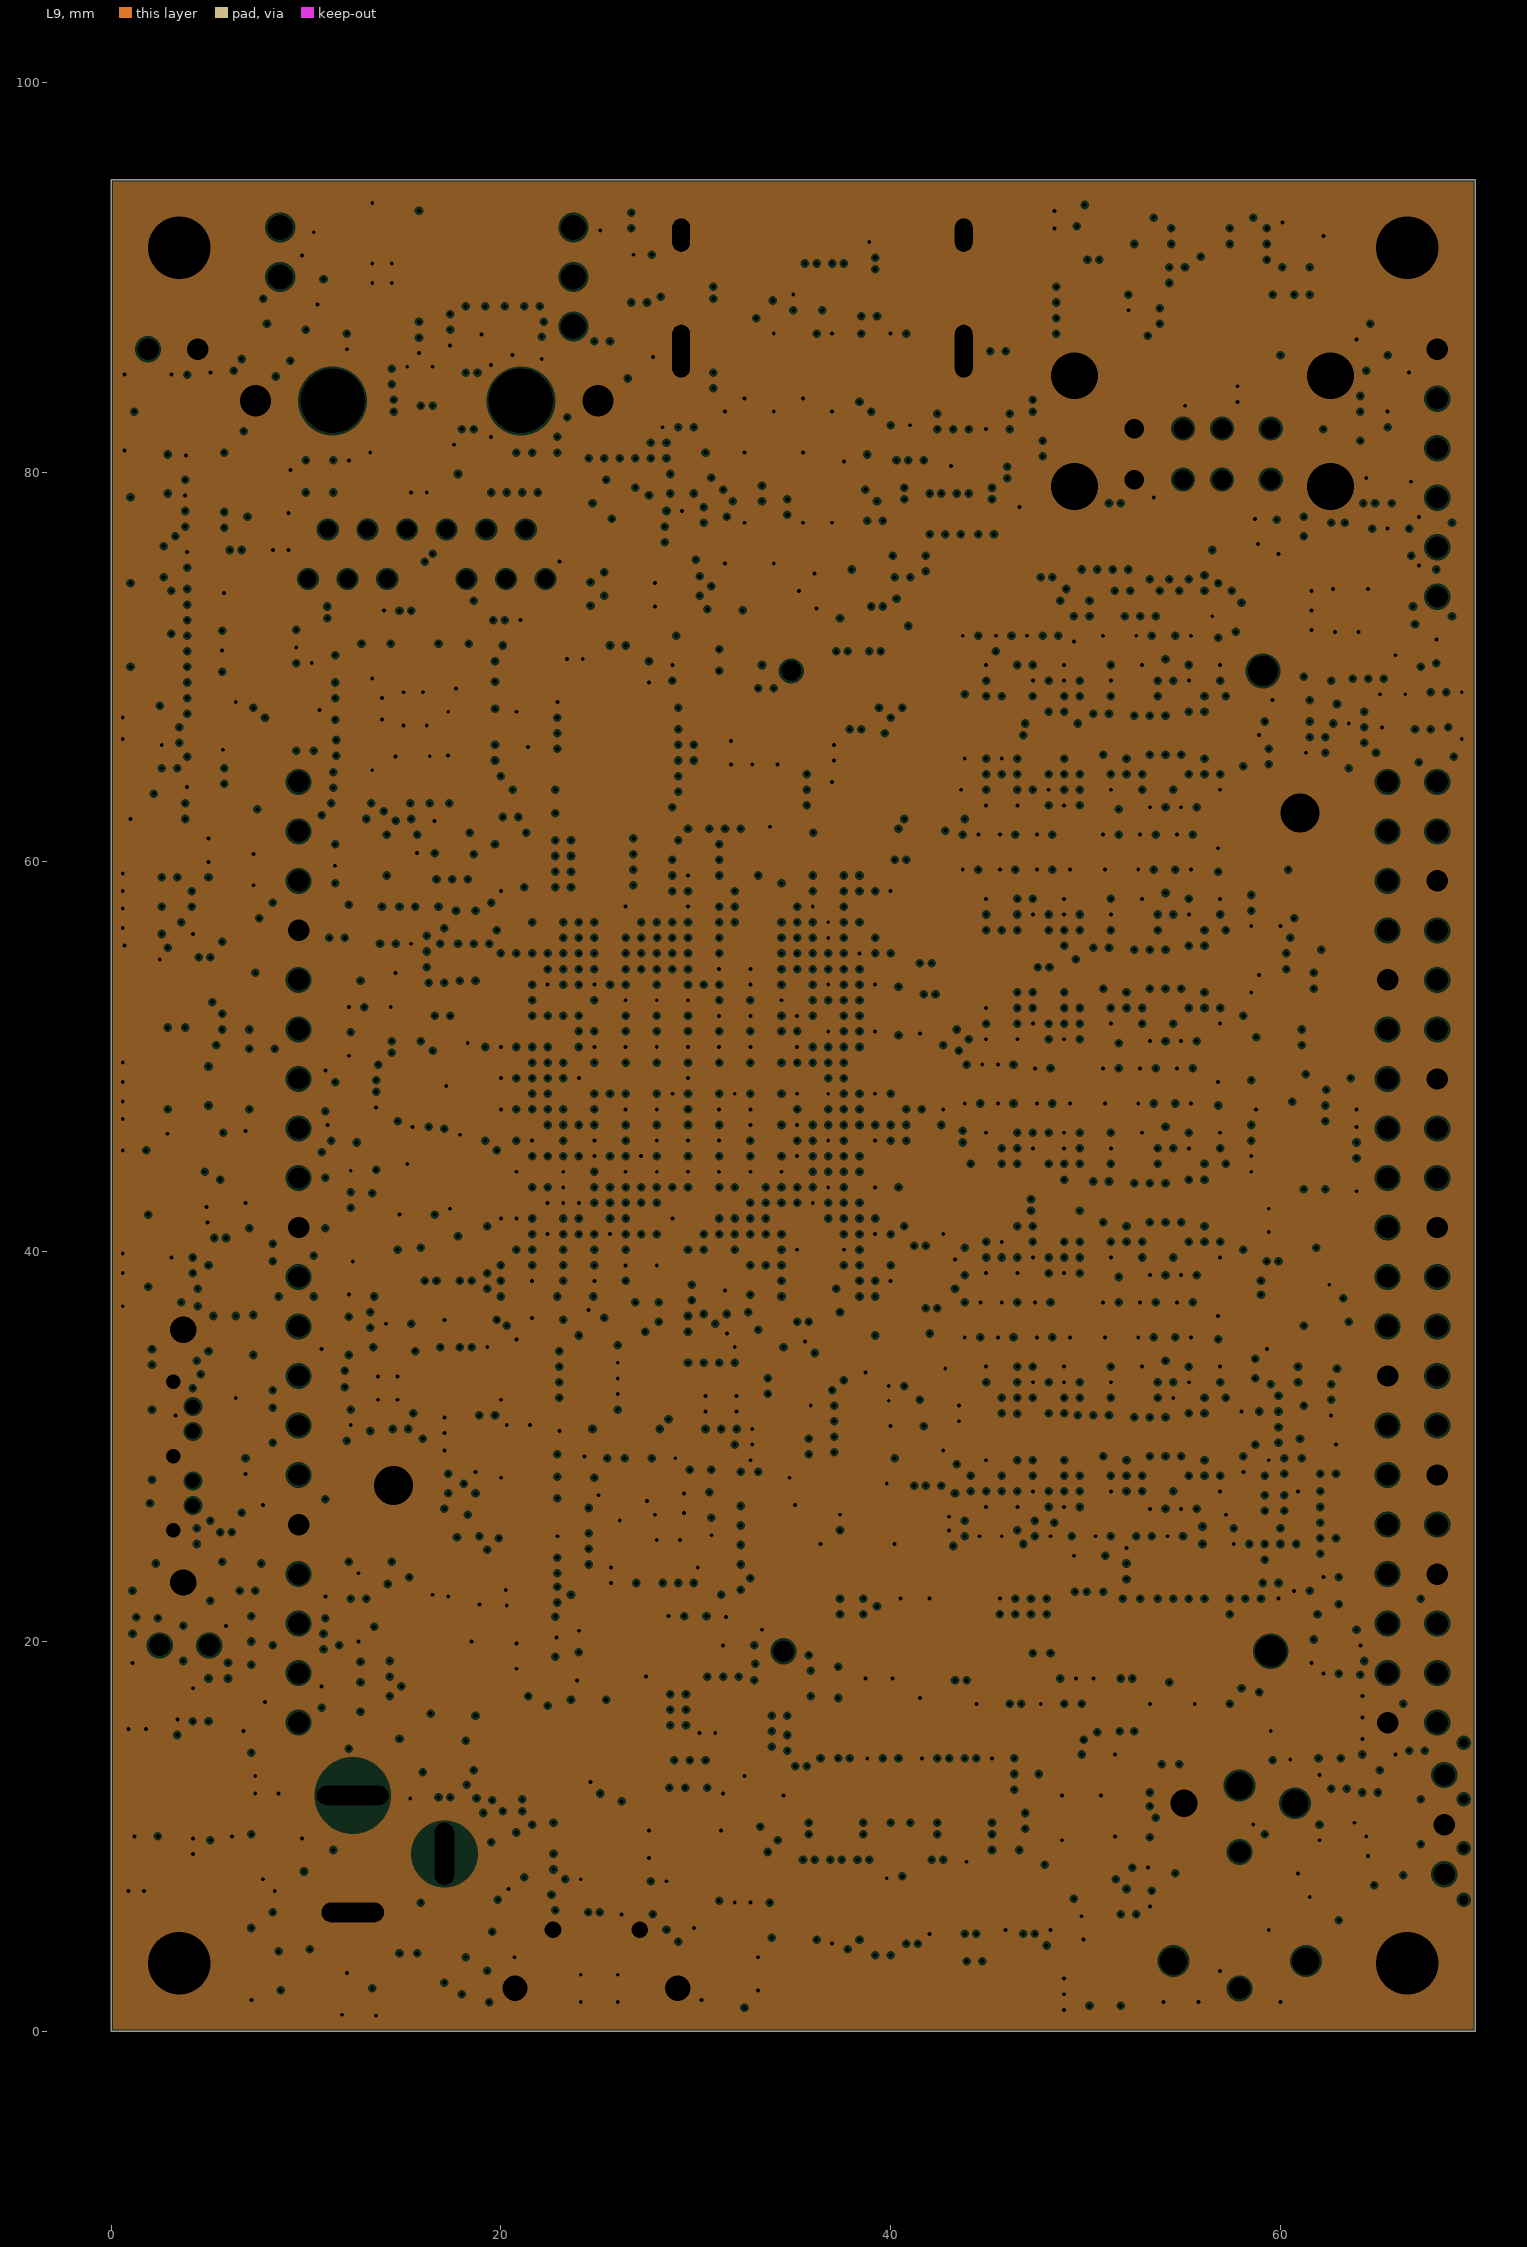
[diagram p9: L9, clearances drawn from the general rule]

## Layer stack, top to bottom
Top Solder: solder mask 0.02, Solder Resist, Dk 4.1
L1: signal copper 0.043
Dielectric1: core 0.074, VT47-1080, Dk 3.95
L2: plane copper 0.018, net GND
Dielectric2: prepreg 0.102, VT-47, Dk 4.12
L3: signal copper 0.018
Dielectric3: core 0.282, VT47-2113, Dk 4.06
L4 (PWR): signal copper 0.018
Dielectric4: prepreg 0.102, VT-47, Dk 4.12
L5 (PWR): signal copper 0.018
Dielectric 8: dielectric 0.282, VT47-2113, Dk 4.06
L6 (PWR): signal copper 0.018
Dielectric 9: dielectric 0.102, VT-47, Dk 4.12
L7 (PWR): signal copper 0.018
Dielectric5: core 0.282, VT47-2113, Dk 4.06
L8: signal copper 0.018
Dielectric6: prepreg 0.102, VT-47, Dk 4.12
L9: plane copper 0.018, net GND
Dielectric7: core 0.074, VT47-1080, Dk 3.95
L10: signal copper 0.043
Bottom Solder: solder mask 0.02, Solder Resist, Dk 4.1

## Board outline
0,0 70,0 70,95 0,95

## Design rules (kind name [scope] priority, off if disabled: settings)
Clearance "Pad Clearance" [IsPad vs IsPad] p1: gap=0.2
Clearance "Clearance Non Plated Holes" [InPadClass('NPTH')] p2: gap=0.5
Clearance "Signal tracks" [IsTrack and not(InNetClass('DIFF100') or InNetClass('DIFF90')) and (Width <= 0.3) vs IsTrack and (Width <= 0.3)] p3: gap=0.16
Clearance "Poly to Poly Inner Layers" [IsRegion AND (OnLayer('L4 (PWR)') OR OnLayer('L5 (PWR)') OR OnLayer('L6 (PWR)') OR OnLayer('L7 (PWR)')) vs IsRegion] p4: gap=0.35
Clearance "Poly to Poly Outer Layers" [IsRegion AND (OnLayer('L1') OR OnLayer('L10')) vs IsRegion or IsTrack] p5: gap=0.14
Clearance "PWR Poly to VIA" [IsRegion AND (OnLayer('L4 (PWR)') OR OnLayer('L5 (PWR)') OR OnLayer('L6 (PWR)') OR OnLayer('L7 (PWR)')) vs IsVia] p6: gap=0.1
Clearance [All] p7: gap=0.1
ComponentClearance "PCIe card model" [InComponent('CR1') vs InComponent('J15') or InComponent('J16')] p1: gap=0 collisioncheckmode=3 verticalgap=0 showdistances=FALSE
ComponentClearance "SIM Card model" [InComponent('CR1') or InComponent('CR3') vs InComponent('J17')] p2: gap=0 collisioncheckmode=3 verticalgap=0 showdistances=FALSE
ComponentClearance "SD Card model to SD slot" [InComponent('CR2') vs InComponent('J13')] p3: gap=0 collisioncheckmode=3 verticalgap=0 showdistances=FALSE
ComponentClearance "FID1 to J9" [InComponent('FID1') vs InComponent('J9')] p4: gap=0 collisioncheckmode=3 verticalgap=0 showdistances=FALSE
ComponentClearance "FID2 to J14" [InComponent('FID2') vs InComponent('J14')] p5: gap=0 collisioncheckmode=3 verticalgap=0 showdistances=FALSE
ComponentClearance "FID3 to J4" [InComponent('FID3') vs InComponent('J4')] p6: gap=0 collisioncheckmode=3 verticalgap=0 showdistances=FALSE
ComponentClearance "FID4 to J6" [InComponent('FID4') vs InComponent('J6')] p7: gap=0 collisioncheckmode=3 verticalgap=0 showdistances=FALSE
ComponentClearance USB0_N [InComponent('R322') vs InComponent('R321') or InComponent('R323')] p8: gap=0 collisioncheckmode=3 verticalgap=0 showdistances=FALSE
ComponentClearance USB0_P [InComponent('R325') vs InComponent('R324') or InComponent('R326')] p9: gap=0 collisioncheckmode=3 verticalgap=0 showdistances=FALSE
ComponentClearance USB1_N [InComponent('R328') vs InComponent('R327') or InComponent('R329')] p10: gap=0 collisioncheckmode=3 verticalgap=0 showdistances=FALSE
ComponentClearance USB1_P [InComponent('R331') vs InComponent('R330') or InComponent('R332')] p11: gap=0 collisioncheckmode=3 verticalgap=0 showdistances=FALSE
ComponentClearance "USB1_N R0805" [InComponent('R294') vs InComponent('R194') or InComponent('R207')] p12: gap=0 collisioncheckmode=3 verticalgap=0 showdistances=FALSE
ComponentClearance "USB1_P R0805" [InComponent('R295') vs InComponent('R297') or InComponent('R298')] p13: gap=0 collisioncheckmode=3 verticalgap=0 showdistances=FALSE
ComponentClearance "USB1_N R0402" [InComponent('R194') vs InComponent('R207')] p14: gap=0 collisioncheckmode=3 verticalgap=0 showdistances=FALSE
ComponentClearance "USB1_P R0402" [InComponent('R297') vs InComponent('R298')] p15: gap=0 collisioncheckmode=3 verticalgap=0 showdistances=FALSE
ComponentClearance CSI_D0_N [InComponent('R33') vs InComponent('R65')] p16: gap=0 collisioncheckmode=3 verticalgap=0 showdistances=FALSE
ComponentClearance CSI_D0_R [InComponent('R71') vs InComponent('R119')] p17: gap=0 collisioncheckmode=3 verticalgap=0 showdistances=FALSE
ComponentClearance CSI_D1_N [InComponent('R120') vs InComponent('R121')] p18: gap=0 collisioncheckmode=3 verticalgap=0 showdistances=FALSE
ComponentClearance CSI_D1_R [InComponent('R122') vs InComponent('R123')] p19: gap=0 collisioncheckmode=3 verticalgap=0 showdistances=FALSE
ComponentClearance CSI_D2_N [InComponent('R125') vs InComponent('R126')] p20: gap=0 collisioncheckmode=3 verticalgap=0 showdistances=FALSE
ComponentClearance CSI_D2_R [InComponent('R127') vs InComponent('R128')] p21: gap=0 collisioncheckmode=3 verticalgap=0 showdistances=FALSE
ComponentClearance LVDS0_CLK_N [InComponent('R129') vs InComponent('R135')] p22: gap=0 collisioncheckmode=3 verticalgap=0 showdistances=FALSE
ComponentClearance LVDS0_CLK_P [InComponent('R136') vs InComponent('R138')] p23: gap=0 collisioncheckmode=3 verticalgap=0 showdistances=FALSE
ComponentClearance CAN [InComponent('U19') vs InComponent('R41') or InComponent('R117')] p24: gap=0 collisioncheckmode=3 verticalgap=0 showdistances=FALSE
ComponentClearance "Reset circuit" [InComponent('U31') vs InComponent('R350')] p25: gap=0 collisioncheckmode=3 verticalgap=0 showdistances=FALSE
ComponentClearance "UART4_TXD PWM selection_1" [InComponent('R366') vs InComponent('R367') or InComponent('R368')] p26: gap=0 collisioncheckmode=3 verticalgap=0 showdistances=FALSE
ComponentClearance "UART4_TXD PWM selection_2" [InComponent('R369') vs InComponent('R367') or InComponent('R368')] p27: gap=0 collisioncheckmode=3 verticalgap=0 showdistances=FALSE
ComponentClearance "1V2_ETH source selection" [InComponent('R354') vs InComponent('R355')] p28: gap=0 collisioncheckmode=3 verticalgap=0 showdistances=FALSE
ComponentClearance "1V2_ETH output selection" [InComponent('R352') vs InComponent('R353')] p29: gap=0 collisioncheckmode=3 verticalgap=0 showdistances=FALSE
ComponentClearance "Beads MCU power" [InComponent('FB29') vs InComponent('FB30')] p30: gap=0 collisioncheckmode=3 verticalgap=0 showdistances=FALSE
ComponentClearance "Beads 5V MPCIe" [InComponent('FB17') vs InComponent('FB37')] p31: gap=0 collisioncheckmode=3 verticalgap=0 showdistances=FALSE
ComponentClearance "Beads 5V USB Bottom" [InComponent('FB38') vs InComponent('FB23')] p32: gap=0 collisioncheckmode=3 verticalgap=0 showdistances=FALSE
ComponentClearance "Beads Audio VDDD" [InComponent('FB20') vs InComponent('FB11')] p33: gap=0 collisioncheckmode=3 verticalgap=0 showdistances=FALSE
ComponentClearance "Beads Audio VDDA" [InComponent('FB26') vs InComponent('FB13')] p34: gap=0 collisioncheckmode=3 verticalgap=0 showdistances=FALSE
ComponentClearance "Beads CAN poer" [InComponent('FB43') vs InComponent('FB44')] p35: gap=0 collisioncheckmode=3 verticalgap=0 showdistances=FALSE
ComponentClearance "Header J1 5V selection" [InComponent('FB34') vs InComponent('FB35')] p36: gap=0 collisioncheckmode=3 verticalgap=0 showdistances=FALSE
ComponentClearance "Header J1 3V3 selection" [InComponent('FB40') vs InComponent('FB42')] p37: gap=0 collisioncheckmode=3 verticalgap=0 showdistances=FALSE
ComponentClearance "Header J2 5V selection" [InComponent('FB31') vs InComponent('FB32')] p38: gap=0 collisioncheckmode=3 verticalgap=0 showdistances=FALSE
ComponentClearance "Header J2 3V3 selection" [InComponent('FB39') vs InComponent('FB41')] p39: gap=0 collisioncheckmode=3 verticalgap=0 showdistances=FALSE
ComponentClearance "Diodes Serial console power" [InComponent('D30') vs InComponent('D38')] p40: gap=0 collisioncheckmode=3 verticalgap=0 showdistances=FALSE
ComponentClearance "MH2 and LED transistor" [InComponent('MH2') vs InComponent('Q6')] p41: gap=0 collisioncheckmode=3 verticalgap=0 showdistances=FALSE
ComponentClearance [All] p42: gap=0.2 collisioncheckmode=3 verticalgap=0.2 showdistances=FALSE
DiffPairsRouting DiffPair_DIFF100DiffPairsRouting [InDifferentialPairClass('DIFF100')] p1: maxlimit=0.25 minlimit=0.21 mostfreqgap=0.25 toplayer_mingap=0.22 toplayer_maxgap=0.22 toplayer_prefgap=0.22 toplayer_minwidth=0.1 toplayer_maxwidth=0.1 toplayer_prefwidth=0.1 midlayer1_maxgap=0.21 midlayer1_prefgap=0.21 midlayer1_minwidth=0.11 midlayer1_maxwidth=0.11 midlayer1_prefwidth=0.11 midlayer2_mingap=0.25 midlayer2_minwidth=0.2 midlayer2_maxwidth=0.2 midlayer2_prefwidth=0.2 midlayer3_mingap=0.25 midlayer3_minwidth=0.2 midlayer3_maxwidth=0.2 midlayer3_prefwidth=0.2 midlayer4_maxgap=0.21 midlayer4_prefgap=0.21 midlayer4_minwidth=0.11 midlayer4_maxwidth=0.11 midlayer4_prefwidth=0.11 midlayer5_mingap=0.25 midlayer5_minwidth=0.2 midlayer5_maxwidth=0.2 midlayer5_prefwidth=0.2 midlayer6_mingap=0.25 midlayer6_minwidth=0.2 midlayer6_maxwidth=0.2 midlayer6_prefwidth=0.2 bottomlayer_mingap=0.22 bottomlayer_maxgap=0.22 bottomlayer_prefgap=0.22 bottomlayer_minwidth=0.1 bottomlayer_maxwidth=0.1 bottomlayer_prefwidth=0.1 maxuncoupledlength=12.3
DiffPairsRouting DiffPair_DIFF90DiffPairsRouting [InDifferentialPairClass('DIFF90')] p2: maxlimit=0.2 minlimit=0.16 mostfreqgap=0.2 toplayer_maxgap=0.16 toplayer_prefgap=0.16 toplayer_minwidth=0.114 toplayer_maxwidth=0.114 toplayer_prefwidth=0.114 midlayer1_mingap=0.19 midlayer1_maxgap=0.19 midlayer1_prefgap=0.19 midlayer1_minwidth=0.13 midlayer1_maxwidth=0.13 midlayer1_prefwidth=0.13 midlayer2_mingap=0.2 midlayer2_minwidth=0.18 midlayer2_maxwidth=0.18 midlayer2_prefwidth=0.18 midlayer3_mingap=0.2 midlayer3_minwidth=0.18 midlayer3_maxwidth=0.18 midlayer3_prefwidth=0.18 midlayer4_mingap=0.19 midlayer4_maxgap=0.19 midlayer4_prefgap=0.19 midlayer4_minwidth=0.13 midlayer4_maxwidth=0.13 midlayer4_prefwidth=0.13 midlayer5_mingap=0.2 midlayer5_minwidth=0.18 midlayer5_maxwidth=0.18 midlayer5_prefwidth=0.18 midlayer6_mingap=0.2 midlayer6_minwidth=0.18 midlayer6_maxwidth=0.18 midlayer6_prefwidth=0.18 bottomlayer_maxgap=0.16 bottomlayer_prefgap=0.16 bottomlayer_minwidth=0.114 bottomlayer_maxwidth=0.114 bottomlayer_prefwidth=0.114 maxuncoupledlength=8.6
DiffPairsRouting [All] p3: maxlimit=0.2 minlimit=0.2 mostfreqgap=0.2 toplayer_minwidth=0.381 toplayer_maxwidth=0.381 toplayer_prefwidth=0.381 midlayer1_minwidth=0.381 midlayer1_maxwidth=0.381 midlayer1_prefwidth=0.381 midlayer2_minwidth=0.381 midlayer2_maxwidth=0.381 midlayer2_prefwidth=0.381 midlayer3_minwidth=0.381 midlayer3_maxwidth=0.381 midlayer3_prefwidth=0.381 midlayer4_minwidth=0.381 midlayer4_maxwidth=0.381 midlayer4_prefwidth=0.381 midlayer5_minwidth=0.381 midlayer5_maxwidth=0.381 midlayer5_prefwidth=0.381 midlayer6_minwidth=0.381 midlayer6_maxwidth=0.381 midlayer6_prefwidth=0.381 bottomlayer_minwidth=0.381 bottomlayer_maxwidth=0.381 bottomlayer_prefwidth=0.381 maxuncoupledlength=0
Height [All] p1: minheight=-8 maxheight=25.4 prefheight=12.7
HoleSize [All] p1: absolutevalues=TRUE maxlimit=10 minlimit=0.2 maxpercent=80.000 minpercent=20.000
HoleToHoleClearance [All] p1: gap=0.3 allowstackedmicrovias=TRUE
MatchedLengths MatchedLengths_Bank0 [InNetClass('DRAM_BANK0')] p1: tolerance=0.254 checknetsindiffpair=FALSE checkdiffpairvsdiffpair=FALSE checkothers=TRUE
MatchedLengths MatchedLengths_Bank1 [InNetClass('DRAM_BANK1')] p2: tolerance=0.254 checknetsindiffpair=FALSE checkdiffpairvsdiffpair=FALSE checkothers=TRUE
MatchedLengths MatchedLengths_Bank2 [InNetClass('DRAM_BANK2')] p3: tolerance=0.254 checknetsindiffpair=FALSE checkdiffpairvsdiffpair=FALSE checkothers=TRUE
MatchedLengths MatchedLengths_Bank3 [InNetClass('DRAM_BANK3')] p4: tolerance=0.254 checknetsindiffpair=FALSE checkdiffpairvsdiffpair=FALSE checkothers=TRUE
MatchedLengths MatchedLengths_Bank4 [InNetClass('DRAM_BANK4')] p5: tolerance=0.254 checknetsindiffpair=FALSE checkdiffpairvsdiffpair=FALSE checkothers=TRUE
MatchedLengths MatchedLengths_Bank5 [InNetClass('DRAM_BANK5')] p6: tolerance=0.254 checknetsindiffpair=FALSE checkdiffpairvsdiffpair=FALSE checkothers=TRUE
MatchedLengths MatchedLengths_Bank6 [InNetClass('DRAM_BANK6')] p7: tolerance=0.254 checknetsindiffpair=FALSE checkdiffpairvsdiffpair=FALSE checkothers=TRUE
MatchedLengths MatchedLengths_Bank7 [InNetClass('DRAM_BANK7')] p8: tolerance=0.254 checknetsindiffpair=FALSE checkdiffpairvsdiffpair=FALSE checkothers=TRUE
MatchedLengths DiffPair_DIFF100MatchedLengths [InDifferentialPairClass('DIFF100')] p9: tolerance=0.127 checknetsindiffpair=TRUE checkdiffpairvsdiffpair=FALSE checkothers=FALSE
MatchedLengths DiffPair_DIFF90MatchedLengths [InDifferentialPairClass('DIFF90')] p10: tolerance=0.127 checknetsindiffpair=TRUE checkdiffpairvsdiffpair=FALSE checkothers=FALSE
MinimumSolderMaskSliver [All] p1: minsoldermaskwidth=0.1
PlaneClearance [All] p1: clearance=0.12
PlaneConnect "GND to J9" [Incomponent('J9')] p1: planeconnectstyle=Relief reliefexpansion=0.5 reliefentries=4 reliefconductorwidth=2 reliefairgap=0.3
PlaneConnect "GND to MH" [Incomponent('MH1') or Incomponent('MH2') or Incomponent('MH3') or Incomponent('MH4') or Incomponent('MH5') or Incomponent('MH6')] p2: planeconnectstyle=Direct reliefexpansion=0.508 reliefentries=4 reliefconductorwidth=0.254 reliefairgap=0.254
PlaneConnect "GND to PAD" [(InNet('GND') and IsPad)] p3: planeconnectstyle=Relief reliefexpansion=0.3 reliefentries=4 reliefconductorwidth=0.5 reliefairgap=0.2
PlaneConnect [All] p4: planeconnectstyle=Direct reliefexpansion=0.2 reliefentries=4 reliefconductorwidth=0.3 reliefairgap=0.2
PolygonConnect [All] p1: connectstyle=Direct reliefconductorwidth=0.254 reliefentries=4 polygonreliefangle="90 Angle" airgapwidth=0.254
RoutingVias [All] p1: holewidth=0.2 width=0.45 viastyle="Through Hole" minholewidth=0.2 minwidth=0.45 maxholewidth=0.5 maxwidth=1
SilkToSilkClearance [All] p1: silktosilkclearance=0.1
SilkToSolderMaskClearance SilkscreenOverComponentPads [IsPad] p1: minsilkscreentomaskgap=0.1 clearancetoexposedcopper=TRUE
SolderMaskExpansion [All] p1: expansion=0.102
UnpouredPolygon [All] p1: allowunpoured=FALSE
Width DiffPair_DIFF100Width [InDifferentialPairClass('DIFF100')] p1: maxlimit=0.2 minlimit=0.1 preferedwidth=0.2 toplayer_maxwidth=0.1 toplayer_prefwidth=0.1 midlayer1_minwidth=0.11 midlayer1_maxwidth=0.11 midlayer1_prefwidth=0.11 midlayer2_minwidth=0.2 midlayer3_minwidth=0.2 midlayer4_minwidth=0.11 midlayer4_maxwidth=0.11 midlayer4_prefwidth=0.11 midlayer5_minwidth=0.2 midlayer6_minwidth=0.2 bottomlayer_maxwidth=0.1 bottomlayer_prefwidth=0.1 minimp=50.000000 maximp=50.000000 favimp=50.000000
Width DiffPair_DIFF90Width [InDifferentialPairClass('DIFF90')] p2: maxlimit=0.2 minlimit=0.114 preferedwidth=0.2 toplayer_maxwidth=0.114 toplayer_prefwidth=0.114 midlayer1_minwidth=0.13 midlayer1_maxwidth=0.13 midlayer1_prefwidth=0.13 midlayer2_minwidth=0.2 midlayer3_minwidth=0.2 midlayer4_minwidth=0.13 midlayer4_maxwidth=0.13 midlayer4_prefwidth=0.13 midlayer5_minwidth=0.2 midlayer6_minwidth=0.2 bottomlayer_maxwidth=0.114 bottomlayer_prefwidth=0.114 minimp=50.000000 maximp=50.000000 favimp=50.000000
Width "Width Power" [InNet('+VIN') OR InNet('+5V') OR InNet('+3V3') OR InNet('+1V5_DDR') OR InNet('+1V375_CORE') OR InNet('+1V375_SOC') OR InNet('+2V5')] p3: maxlimit=4 minlimit=0.2 preferedwidth=0.4
Width "Width Ground" [InNet('GND')] p4: maxlimit=40 minlimit=0.23 preferedwidth=0.4
Width [All] p5: maxlimit=2 minlimit=0.114 preferedwidth=0.15 toplayer_prefwidth=0.12 midlayer1_minwidth=0.12 midlayer1_prefwidth=0.12 midlayer2_minwidth=0.15 midlayer3_minwidth=0.15 midlayer4_minwidth=0.12 midlayer4_prefwidth=0.12 midlayer5_minwidth=0.15 midlayer6_minwidth=0.15 bottomlayer_prefwidth=0.12 minimp=50.000000 maximp=50.000000 favimp=50.000000
19 further rules are at their usual default settings.

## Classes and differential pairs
net class VID_IN_CSI1: I2C3_CSI1_SCL I2C3_CSI1_SDA VID_IN_CSI1_D0 VID_IN_CSI1_D1 VID_IN_CSI1_D2 VID_IN_CSI1_D3 VID_IN_CSI1_D4 VID_IN_CSI1_D5 VID_IN_CSI1_D6 VID_IN_CSI1_D7 VID_IN_CSI1_D8 VID_IN_CSI1_D9 VID_IN_CSI1_D10 VID_IN_CSI1_D11 VID_IN_CSI1_D12 VID_IN_CSI1_D13 VID_IN_CSI1_D14 VID_IN_CSI1_D15 VID_IN_CSI1_D16 VID_IN_CSI1_D17 VID_IN_CSI1_D18 VID_IN_CSI1_D19 VID_IN_CSI1_DE VID_IN_CSI1_HSYNC VID_IN_CSI1_INT VID_IN_CSI1_INT2 VID_IN_CSI1_PIXCLK VID_IN_CSI1_PIXCLK_R VID_IN_CSI1_RSTN_R VID_IN_CSI1_VSYNC
net class SD2: SD2_ACT SD2_CD SD2_CLK SD2_CLK_R SD2_CMD SD2_CMD_R SD2_DATA0 SD2_DATA1 SD2_DATA2 SD2_DATA3 SD2_WP
net class UART5: UART5_RXD UART5_TXD
net class UART4: UART4_RXD UART4_TXD
net class UART3: UART3_CTS UART3_RTS UART3_RXD UART3_TXD
net class UART2: UART2_RXD UART2_TXD
net class I2C3: I2C3_SCL I2C3_SDA
net class I2C2: I2C2_SCL I2C2_SDA
net class I2C1: I2C1_SCL I2C1_SDA
net class CSPI3: CSPI3_CLK CSPI3_CLK_R CSPI3_CS0 CSPI3_CS2 CSPI3_MCU_CLK CSPI3_MCU_CS0 CSPI3_MCU_ENN CSPI3_MCU_MISO CSPI3_MCU_MOSI CSPI3_MISO CSPI3_MOSI
net class CSPI2: CSPI2_CLK CSPI2_CLK_R CSPI2_CS0 CSPI2_MISO CSPI2_MOSI
net class CSPI1: CSPI1_CLK CSPI1_CLK_R CSPI1_CS0 CSPI1_CS1 CSPI1_MISO CSPI1_MOSI
net class AUD3: AUD3_CLK AUD3_CLK_R AUD3_RXD AUD3_TXC AUD3_TXC_R AUD3_TXD AUD3_TXFS
net class TS: TS_X+ TS_X- TS_Y+ TS_Y-
net class "CSI / LVDS": CSI_CLK0_R_N CSI_CLK0_R_P CSI_D0_R_N CSI_D0_R_P CSI_D1_R_N CSI_D1_R_P I2C2_CSI_SCL I2C2_CSI_SDA LVDS0_CLK_R_N LVDS0_CLK_R_P
pad class NPTH: J6- J14-5 J14-7 J15-55 J15-56 J16-7 J16-8
differential pair class DIFF100: CAN CSI_CLK0 CSI_CLK0_R CSI_D0 CSI_D0_R CSI_D1 CSI_D1_R DRAM_CLK0 DRAM_CLK1 DRAM_DQS0 DRAM_DQS1 DRAM_DQS2 DRAM_DQS3 DRAM_DQS4 DRAM_DQS5 DRAM_DQS6 DRAM_DQS7 HDMI_CLK HDMI_D0 HDMI_D1 HDMI_D2 LVDS0_CLK LVDS0_CLK_R LVDS0_TX0 LVDS0_TX1 LVDS0_TX2 LVDS0_TX3 PCIE_CLK PCIE_CLK_C SATA_C_RX SATA_C_TX SATA_RX SATA_TX TRD0 TRD1 TRD2 TRD3
differential pair class DIFF90: PCIE_C_TX PCIE_RX PCIE_TX USB0 USB0_OTG USB0_OTG_L USB1 USB1_HUB USB_BOT USB_BOT_L USB_HDR USB_HDR_L USB_MCU USB_MCU_R USB_MPCIE USB_MPCIE_L USB_TOP USB_TOP_L USBDN1 USBDN2 USBDN3
net class USB1: USB1_HUB_N USB1_HUB_P USB1_N USB1_P USB_BOT_L_N USB_BOT_L_P USB_BOT_N USB_BOT_P USB_HDR_L_N USB_HDR_L_P USB_HDR_N USB_HDR_P USB_MCU_N USB_MCU_P USB_MCU_R_N USB_MCU_R_P USB_MPCIE_L_N USB_MPCIE_L_P USB_MPCIE_N USB_MPCIE_OC USB_MPCIE_P USB_TOP_L_N USB_TOP_L_P USB_TOP_N USB_TOP_P USBDN1_N USBDN1_OC USBDN1_P USBDN1_PWR_EN USBDN2_N USBDN2_OC USBDN2_P USBDN2_PWR_EN USBDN3_N USBDN3_OC USBDN3_P
net class USB0: USB0_CHD USB0_ID USB0_ID_BUFF_EN USB0_N USB0_OTG_L_N USB0_OTG_L_P USB0_OTG_N USB0_OTG_P USB0_P USB_OC
net class UART1: UART1_CTS UART1_CTS_FTDI UART1_RTS UART1_RTS_FTDI UART1_RXD UART1_RXD_FTDI UART1_TXD UART1_TXD_FTDI
net class SATA: SATA_C_RX_N SATA_C_RX_P SATA_C_TX_N SATA_C_TX_P SATA_REXT SATA_RX_N SATA_RX_P SATA_TX_N SATA_TX_P
net class DIFF100: CAN_N CAN_P CSI_CLK0_N CSI_CLK0_P CSI_CLK0_R_N CSI_CLK0_R_P CSI_D0_N CSI_D0_P CSI_D0_R_N CSI_D0_R_P CSI_D1_N CSI_D1_P CSI_D1_R_N CSI_D1_R_P DRAM_CLK0_N DRAM_CLK0_P DRAM_CLK1_N DRAM_CLK1_P DRAM_DQS0_N DRAM_DQS0_P DRAM_DQS1_N DRAM_DQS1_P DRAM_DQS2_N DRAM_DQS2_P DRAM_DQS3_N DRAM_DQS3_P DRAM_DQS4_N DRAM_DQS4_P DRAM_DQS5_N DRAM_DQS5_P DRAM_DQS6_N DRAM_DQS6_P DRAM_DQS7_N DRAM_DQS7_P HDMI_CLK_N HDMI_CLK_P HDMI_D0_N HDMI_D0_P HDMI_D1_N HDMI_D1_P HDMI_D2_N HDMI_D2_P LVDS0_CLK_N LVDS0_CLK_P LVDS0_CLK_R_N LVDS0_CLK_R_P LVDS0_TX0_N LVDS0_TX0_P LVDS0_TX1_N LVDS0_TX1_P LVDS0_TX2_N LVDS0_TX2_P LVDS0_TX3_N LVDS0_TX3_P PCIE_CLK_C_N PCIE_CLK_C_P PCIE_CLK_N PCIE_CLK_P SATA_C_RX_N SATA_C_RX_P SATA_C_TX_N SATA_C_TX_P SATA_RX_N SATA_RX_P SATA_TX_N SATA_TX_P TRD0_N TRD0_P TRD1_N TRD1_P TRD2_N TRD2_P TRD3_N TRD3_P
net class DIFF90: PCIE_C_TX_N PCIE_C_TX_P PCIE_RX_N PCIE_RX_P PCIE_TX_N PCIE_TX_P USB0_N USB0_OTG_L_N USB0_OTG_L_P USB0_OTG_N USB0_OTG_P USB0_P USB1_HUB_N USB1_HUB_P USB1_N USB1_P USB_BOT_L_N USB_BOT_L_P USB_BOT_N USB_BOT_P USB_HDR_L_N USB_HDR_L_P USB_HDR_N USB_HDR_P USB_MCU_N USB_MCU_P USB_MCU_R_N USB_MCU_R_P USB_MPCIE_L_N USB_MPCIE_L_P USB_MPCIE_N USB_MPCIE_P USB_TOP_L_N USB_TOP_L_P USB_TOP_N USB_TOP_P USBDN1_N USBDN1_P USBDN2_N USBDN2_P USBDN3_N USBDN3_P
net class GPIO: CPU_GPIO0 CPU_GPIO1 CPU_GPIO2
net class PCIE: PCIE_C_TX_N PCIE_C_TX_P PCIE_CLK_C_N PCIE_CLK_C_P PCIE_CLK_N PCIE_CLK_P PCIE_RSTN_R PCIE_RX_N PCIE_RX_P PCIE_TX_N PCIE_TX_P PCIE_WAKE PCIE_WDISN
net class FLEXCAN: CAN_N CAN_P FLEXCAN1_RX FLEXCAN1_STBY FLEXCAN1_TX FLEXCAN2_RX FLEXCAN2_TX SPLIT_R
net class BUTTONS: USER_BTN_1 USER_BTN_2 USER_BTN_3
net class MIPI_CSI: CSI_CLK0_N CSI_CLK0_P CSI_D0_N CSI_D0_P CSI_D1_N CSI_D1_P CSI_GPIO0 CSI_GPIO1 CSI_REXT
net class DRAM_A[15..0]: DRAM_A0 DRAM_A1 DRAM_A2 DRAM_A3 DRAM_A4 DRAM_A5 DRAM_A6 DRAM_A7 DRAM_A8 DRAM_A9 DRAM_A10 DRAM_A11 DRAM_A12 DRAM_A13 DRAM_A14 DRAM_A15
net class DRAM_ADDR_CTRL: DRAM_A0 DRAM_A1 DRAM_A2 DRAM_A3 DRAM_A4 DRAM_A5 DRAM_A6 DRAM_A7 DRAM_A8 DRAM_A9 DRAM_A10 DRAM_A11 DRAM_A12 DRAM_A13 DRAM_A14 DRAM_A15 DRAM_CAS_B DRAM_CS0_B DRAM_RAS_B DRAM_RESET_B DRAM_SDBA0 DRAM_SDBA1 DRAM_SDBA2 DRAM_SDCKE0 DRAM_SDODT0 DRAM_WE_B
net class DRAM_BANK0: DRAM_D0 DRAM_D1 DRAM_D2 DRAM_D3 DRAM_D4 DRAM_D5 DRAM_D6 DRAM_D7 DRAM_DQM0 DRAM_DQS0_N DRAM_DQS0_P
net class DRAM_BANK1: DRAM_D8 DRAM_D9 DRAM_D10 DRAM_D11 DRAM_D12 DRAM_D13 DRAM_D14 DRAM_D15 DRAM_DQM1 DRAM_DQS1_N DRAM_DQS1_P
net class DRAM_BANK2: DRAM_D16 DRAM_D17 DRAM_D18 DRAM_D19 DRAM_D20 DRAM_D21 DRAM_D22 DRAM_D23 DRAM_DQM2 DRAM_DQS2_N DRAM_DQS2_P
net class DRAM_BANK3: DRAM_D24 DRAM_D25 DRAM_D26 DRAM_D27 DRAM_D28 DRAM_D29 DRAM_D30 DRAM_D31 DRAM_DQM3 DRAM_DQS3_N DRAM_DQS3_P
net class DRAM_BANK4: DRAM_D32 DRAM_D33 DRAM_D34 DRAM_D35 DRAM_D36 DRAM_D37 DRAM_D38 DRAM_D39 DRAM_DQM4 DRAM_DQS4_N DRAM_DQS4_P
net class DRAM_BANK5: DRAM_D40 DRAM_D41 DRAM_D42 DRAM_D43 DRAM_D44 DRAM_D45 DRAM_D46 DRAM_D47 DRAM_DQM5 DRAM_DQS5_N DRAM_DQS5_P
net class DRAM_BANK6: DRAM_D48 DRAM_D49 DRAM_D50 DRAM_D51 DRAM_D52 DRAM_D53 DRAM_D54 DRAM_D55 DRAM_DQM6 DRAM_DQS6_N DRAM_DQS6_P
net class DRAM_BANK7: DRAM_D56 DRAM_D57 DRAM_D58 DRAM_D59 DRAM_D60 DRAM_D61 DRAM_D62 DRAM_D63 DRAM_DQM7 DRAM_DQS7_N DRAM_DQS7_P
net class DRAM_D[63..0]: DRAM_D0 DRAM_D1 DRAM_D2 DRAM_D3 DRAM_D4 DRAM_D5 DRAM_D6 DRAM_D7 DRAM_D8 DRAM_D9 DRAM_D10 DRAM_D11 DRAM_D12 DRAM_D13 DRAM_D14 DRAM_D15 DRAM_D16 DRAM_D17 DRAM_D18 DRAM_D19 DRAM_D20 DRAM_D21 DRAM_D22 DRAM_D23 DRAM_D24 DRAM_D25 DRAM_D26 DRAM_D27 DRAM_D28 DRAM_D29 DRAM_D30 DRAM_D31 DRAM_D32 DRAM_D33 DRAM_D34 DRAM_D35 DRAM_D36 DRAM_D37 DRAM_D38 DRAM_D39 DRAM_D40 DRAM_D41 DRAM_D42 DRAM_D43 DRAM_D44 DRAM_D45 DRAM_D46 DRAM_D47 DRAM_D48 DRAM_D49 DRAM_D50 DRAM_D51 DRAM_D52 DRAM_D53 DRAM_D54 DRAM_D55 DRAM_D56 DRAM_D57 DRAM_D58 DRAM_D59 DRAM_D60 DRAM_D61 DRAM_D62 DRAM_D63
net class DRAM_OTHERS: ZQPAD
net class DRAM_SDCLK: DRAM_CLK0_N DRAM_CLK0_P DRAM_CLK1_N DRAM_CLK1_P
net class ENET: ENET_LED_LINK ENET_LED_RX LED1 LED2 TRD0_N TRD0_P TRD1_N TRD1_P TRD2_N TRD2_P TRD3_N TRD3_P
net class GPIO_MISC: COMP_INT GPIO_OR_CLK GYRO_INT IR_RCV MCU_ISPN MCU_RSTINN MCU_SWDIO MCU_SWDIO_SEL TEMP_ALERT
net class HDMI: HDMI_CEC HDMI_CEC_CON HDMI_CEC_IN HDMI_CLK_N HDMI_CLK_P HDMI_D0_N HDMI_D0_P HDMI_D1_N HDMI_D1_P HDMI_D2_N HDMI_D2_P HDMI_DDC HDMI_HPD HDMI_HPD_BUFF HDMI_HPD_CON HDMI_HPD_R HDMI_SCL_CON HDMI_SCL_CON_R HDMI_SDA_CON HDMI_SDA_CON_R
net class JTAG: JTAG_MOD JTAG_NTRST JTAG_TCK JTAG_TCK_R JTAG_TDI JTAG_TDI_R JTAG_TDO JTAG_TDO_R JTAG_TMS
net class LVDS: LVDS0_CLK_N LVDS0_CLK_P LVDS0_TX0_N LVDS0_TX0_P LVDS0_TX1_N LVDS0_TX1_P LVDS0_TX2_N LVDS0_TX2_P LVDS0_TX3_N LVDS0_TX3_P
net class PWM: GPIO_OR_PWM_1 GPIO_OR_PWM_2 GPIO_OR_PWM_3 GPIO_OR_PWM_4
net class RGMII_MISC: ENET_REF_CLK ENET_REF_CLK_R ETH_ISET RGMII_INT RGMII_INT_R RGMII_MDC RGMII_MDIO RGMII_R_MDC RGMII_R_MDIO
net class RGMII_RXD: RGMII_R_RXCLK RGMII_RXCLK RGMII_RXD0 RGMII_RXD1 RGMII_RXD2 RGMII_RXD3 RGMII_RXDV
net class RGMII_TXD: RGMII_R_TXCLK RGMII_TXCLK RGMII_TXD0 RGMII_TXD1 RGMII_TXD2 RGMII_TXD3 RGMII_TXEN
net class SIM: +MPCIE_SIM_PWR +MPCIE_SIM_VPP MPCIE_SIM_C4 MPCIE_SIM_C4_R MPCIE_SIM_C8 MPCIE_SIM_C8_R MPCIE_SIM_CLK MPCIE_SIM_DATA MPCIE_SIM_RST
net class USER_LEDS: USER_LED_1 USER_LED_2 USER_LED_3 USER_LED_4 USER_LED_5 USER_LED_6 USER_LED_7 USER_LED_8
differential pair CAN: +CAN_P -CAN_N
differential pair CSI_D1_R: +CSI_D1_R_P -CSI_D1_R_N
differential pair CSI_D0_R: +CSI_D0_R_P -CSI_D0_R_N
differential pair CSI_CLK0_R: +CSI_CLK0_R_P -CSI_CLK0_R_N
differential pair USB_MCU_R: +USB_MCU_R_P -USB_MCU_R_N
differential pair USBDN3: +USBDN3_P -USBDN3_N
differential pair USB_MCU: +USB_MCU_P -USB_MCU_N
differential pair LVDS0_CLK_R: +LVDS0_CLK_R_P -LVDS0_CLK_R_N
differential pair USB0: +USB0_P -USB0_N
differential pair TRD3: +TRD3_P -TRD3_N
differential pair TRD2: +TRD2_P -TRD2_N
differential pair TRD1: +TRD1_P -TRD1_N
differential pair TRD0: +TRD0_P -TRD0_N
differential pair SATA_TX: +SATA_TX_P -SATA_TX_N
differential pair SATA_RX: +SATA_RX_P -SATA_RX_N
differential pair CSI_CLK0: +CSI_CLK0_P -CSI_CLK0_N
differential pair CSI_D0: +CSI_D0_P -CSI_D0_N
differential pair CSI_D1: +CSI_D1_P -CSI_D1_N
differential pair USB1: +USB1_P -USB1_N
differential pair USB_MPCIE: +USB_MPCIE_P -USB_MPCIE_N
differential pair PCIE_CLK: +PCIE_CLK_P -PCIE_CLK_N
differential pair PCIE_RX: +PCIE_RX_P -PCIE_RX_N
differential pair PCIE_TX: +PCIE_TX_P -PCIE_TX_N
differential pair DRAM_CLK0: +DRAM_CLK0_P -DRAM_CLK0_N
differential pair DRAM_CLK1: +DRAM_CLK1_P -DRAM_CLK1_N
differential pair DRAM_DQS0: +DRAM_DQS0_P -DRAM_DQS0_N
differential pair DRAM_DQS1: +DRAM_DQS1_P -DRAM_DQS1_N
differential pair DRAM_DQS2: +DRAM_DQS2_P -DRAM_DQS2_N
differential pair DRAM_DQS3: +DRAM_DQS3_P -DRAM_DQS3_N
differential pair DRAM_DQS4: +DRAM_DQS4_P -DRAM_DQS4_N
differential pair DRAM_DQS5: +DRAM_DQS5_P -DRAM_DQS5_N
differential pair DRAM_DQS6: +DRAM_DQS6_P -DRAM_DQS6_N
differential pair DRAM_DQS7: +DRAM_DQS7_P -DRAM_DQS7_N
differential pair HDMI_CLK: +HDMI_CLK_P -HDMI_CLK_N
differential pair HDMI_D0: +HDMI_D0_P -HDMI_D0_N
differential pair HDMI_D1: +HDMI_D1_P -HDMI_D1_N
differential pair HDMI_D2: +HDMI_D2_P -HDMI_D2_N
differential pair LVDS0_CLK: +LVDS0_CLK_P -LVDS0_CLK_N
differential pair LVDS0_TX0: +LVDS0_TX0_P -LVDS0_TX0_N
differential pair LVDS0_TX1: +LVDS0_TX1_P -LVDS0_TX1_N
differential pair LVDS0_TX2: +LVDS0_TX2_P -LVDS0_TX2_N
differential pair LVDS0_TX3: +LVDS0_TX3_P -LVDS0_TX3_N
differential pair PCIE_C_TX: +PCIE_C_TX_P -PCIE_C_TX_N
differential pair PCIE_CLK_C: +PCIE_CLK_C_P -PCIE_CLK_C_N
differential pair SATA_C_RX: +SATA_C_RX_P -SATA_C_RX_N
differential pair SATA_C_TX: +SATA_C_TX_P -SATA_C_TX_N
differential pair USBDN1: +USBDN1_P -USBDN1_N
differential pair USBDN2: +USBDN2_P -USBDN2_N
differential pair USB_HDR: +USB_HDR_P -USB_HDR_N
differential pair USB_HDR_L: +USB_HDR_L_P -USB_HDR_L_N
differential pair USB_MPCIE_L: +USB_MPCIE_L_P -USB_MPCIE_L_N
differential pair USB0_OTG_L: +USB0_OTG_L_P -USB0_OTG_L_N
differential pair USB0_OTG: +USB0_OTG_P -USB0_OTG_N
differential pair USB1_HUB: +USB1_HUB_P -USB1_HUB_N
differential pair USB_BOT_L: +USB_BOT_L_P -USB_BOT_L_N
differential pair USB_BOT: +USB_BOT_P -USB_BOT_N
differential pair USB_TOP_L: +USB_TOP_L_P -USB_TOP_L_N
differential pair USB_TOP: +USB_TOP_P -USB_TOP_N

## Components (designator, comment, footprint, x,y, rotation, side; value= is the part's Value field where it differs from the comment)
C1 "220n" C0201 44.2,24.9 r0 top
C2 "220n" C0201 46,24.9 r180 top
C3 "220n" C0201 53.2,36.1 r180 top
C4 "220n" C0201 47.8,24.9 r0 top
C5 "220n" C0201 47.8,36.9 r180 top
C6 "220n" C0201 53.2,48.1 r180 top
C7 "100n" C0201 39.2,40.3 r0 bottom
C8 "220n" C0201 47.8,48.9 r180 top
C9 "220n" C0201 53.2,60.1 r180 top
C10 "220n" C0201 47.8,60.9 r180 top
C11 "220n" C0201 53.2,72.1 r180 top
C12 "220n" C0201 49.3,24.9 r180 top
C13 "100n" C0201 58.6,34 r0 top
C14 "100n" C0201 60.4,30.8 r270 top
C15 "100n" C0201 58.7,29.2 r270 top
C16 "100n" C0201 61.5,27 r270 top
C17 "100n" C0201 58.8,27.2 r270 top
C18 "100n" C0201 61.1,24.2 r270 top
C19 "10u" C0603 59.3,52.5 r90 top
C20 "22u" C0603 63,26.9 r90 top
C21 "220n" C0201 52.9,24.9 r180 top
C22 "220n" C0201 54.7,24.9 r180 top
C23 "220n" C0201 44.2,36.1 r180 top
C24 "220n" C0201 46,36.1 r180 top
C25 "220n" C0201 47.8,36.1 r180 top
C26 "220n" C0201 55,36.1 r0 top
C27 "22u" C0603 42.3,26.5 r270 top
C28 "22u" C0603 42.6,39.4 r90 top
C29 "22u" C0603 59.2,45.3 r270 top
C30 "220n" C0201 56.8,36.1 r0 top
C31 "22u" C0603 42.6,63.3 r90 top
C32 "22u" C0603 59.3,57.1 r270 top
C33 "22u" C0603 42.6,49 r270 top
C34 "220n" C0201 44.2,36.9 r0 top
C35 "220n" C0201 46,36.9 r180 top
C36 "220n" C0201 51.4,36.9 r180 top
C37 "220n" C0201 53.2,36.9 r180 top
C38 "220n" C0201 55,36.9 r180 top
C39 "220n" C0201 44.2,48.1 r180 top
C40 "220n" C0201 46,48.1 r180 top
C41 "220n" C0201 47.8,48.1 r180 top
C42 "220n" C0201 55,48.1 r0 top
C43 "220n" C0201 56.8,48.1 r0 top
C44 "220n" C0201 44.2,48.9 r0 top
C45 "220n" C0201 46,48.9 r180 top
C46 "220n" C0201 51.4,48.9 r180 top
C47 "220n" C0201 53.2,48.9 r180 top
C48 "220n" C0201 55,48.9 r180 top
C49 "220n" C0201 44.2,60.1 r180 top
C50 "220n" C0201 46,60.1 r180 top
C51 "220n" C0201 47.8,60.1 r180 top
C52 "220n" C0201 55,60.1 r0 top
C53 "220n" C0201 56.8,60.1 r0 top
C54 "220n" C0201 44.2,60.9 r0 top
C55 "220n" C0201 46,60.9 r180 top
C56 "220n" C0201 51.4,60.9 r180 top
C57 "220n" C0201 53.2,60.9 r180 top
C58 "220n" C0201 55,60.9 r180 top
C59 "220n" C0201 44.2,72.1 r180 top
C60 "220n" C0201 46,72.1 r180 top
C61 "220n" C0201 25.3,44.1 r90 bottom
C62 "220n" C0201 24.3,44.1 r90 bottom
C63 "100n" C0402 18.2,39.1 r180 top
C64 "220n" C0201 24,43.1 r180 bottom
C65 "100n" C0402 18.2,40.2 r180 top
C66 "100n" C0402 17.7,37.4 r270 top
C67 "100n" C0402 18.7,37.4 r270 top
C68 "220n" C0201 23.7,44.1 r270 bottom
C69 "10n" C0402 17.6,49.1 r180 top
C70 "10n" C0402 17.6,50.1 r180 top
C71 "10n" C0402 17.6,47.9 r180 top
C72 "10n" C0402 17.6,46.9 r180 top
C73 "220n" C0201 24,45.4 r0 bottom
C74 "100n" C0201 58.8,23.5 r180 top
C75 "220n" C0201 24,46 r0 bottom
C76 "220n" C0201 28.5,44.1 r90 bottom
C77 "220n" C0201 29.1,44.1 r90 bottom
C78 "4u7" C0402 21.8,37.3 r180 bottom
C79 "220n" C0201 35.2,43.8 r0 bottom
C80 "10u" C0603 20.1,46.5 r180 bottom
C81 "220n" C0201 23.9,48.1 r90 bottom
C82 "220n" C0201 25.6,47.6 r0 bottom
C83 "18p" C0402 17.4,45.2 r90 top
C84 "18p" C0402 17.4,43.2 r270 top
C85 "100n" C0201 55.5,22.9 r0 top
C86 "100n" C0201 54.2,22.9 r180 top
C87 "100n" C0402 3.6,38.8 r90 bottom
C88 "100u / 10V" C2312 26.6,9.5 r0 top
C89 "100n" C0402 12.2,37.2 r0 bottom
C90 "220n" C0201 25.9,50.3 r90 bottom
C91 "220n" C0201 26.9,50.3 r90 bottom
C92 "220n" C0201 27.5,50.3 r90 bottom
C93 "220n" C0201 28.5,50.3 r90 bottom
C94 "220n" C0201 29.1,50.3 r90 bottom
C95 "220n" C0201 31.7,50.3 r90 bottom
C96 "22u" C0603_small 25.6,48.9 r180 bottom
C97 "220n" C0201 26.9,47.5 r270 bottom
C98 "220n" C0201 27.5,47.5 r270 bottom
C99 "220n" C0201 28.8,47.6 r180 bottom
C100 "220n" C0201 31.6,47.4 r270 bottom
C101 "22u" C0603_small 28.2,48.9 r0 bottom
C102 "220n" C0201 26.9,46.3 r270 bottom
C103 "220n" C0201 27.5,46.3 r270 bottom
C104 "220n" C0201 28.8,46.2 r180 bottom
C105 "220n" C0201 31.6,46.2 r270 bottom
C106 "22u" C0603_small 30.4,47.1 r90 bottom
C107 "220n" C0201 28.5,45.3 r90 bottom
C108 "220n" C0201 29.1,45.3 r90 bottom
C109 "220n" C0201 31.7,44.9 r270 bottom
C110 "220n" C0201 32.3,44.9 r270 bottom
C111 "22u" C0603_small 30.4,44.5 r270 bottom
C112 "220n" C0201 32.4,46.2 r90 bottom
C113 "220n" C0201 33.3,46.2 r90 bottom
C114 "220n" C0201 32.4,47.4 r270 bottom
C115 "220n" C0201 33.3,47.4 r270 bottom
C116 "220n" C0201 32.3,50.3 r90 bottom
C117 "220n" C0201 33.3,50.3 r90 bottom
C118 "22u" C0603_small 32.5,48.9 r180 bottom
C119 "220n" C0201 25.9,51.5 r270 bottom
C120 "220n" C0201 26.9,51.5 r270 bottom
C121 "220n" C0201 27.5,51.5 r270 bottom
C122 "220n" C0201 28.5,51.5 r270 bottom
C123 "220n" C0201 29.1,51.5 r270 bottom
C124 "220n" C0201 31.7,51.5 r90 bottom
C125 "220n" C0201 32.3,51.5 r90 bottom
C126 "220n" C0201 33.3,51.5 r90 bottom
C127 "22u" C0603_small 30.4,49.7 r270 bottom
C128 "22u" C0603_small 23.4,52.9 r180 bottom
C129 "22u" C0603_small 25.6,56.7 r90 bottom
C130 "220n" C0201 25.9,52.9 r90 bottom
C131 "220n" C0201 26.9,52.7 r90 bottom
C132 "220n" C0201 27.5,52.7 r90 bottom
C133 "220n" C0201 28.5,52.7 r90 bottom
C134 "220n" C0201 29.1,52.7 r90 bottom
C135 "22u" C0603_small 30.4,52.3 r90 bottom
C136 "220n" C0201 25.9,44.1 r270 bottom
C137 "22u" C0603 20.1,48.1 r180 bottom
C138 "220n" C0201 28.8,47 r180 bottom
C139 "10n" C0201 25.9,46.5 r90 bottom
C140 "220n" C0201 27.2,45.4 r0 bottom
C141 "22u" C0603 24,39.4 r270 bottom
C142 "220n" C0201 25.3,46.5 r270 bottom
C143 "220n" C0201 25.6,45.4 r180 bottom
C144 "220n" C0201 30.5,54.1 r0 bottom
C145 "220n" C0201 30.4,42.8 r0 bottom
C146 "220n" C0201 28.8,53.7 r180 bottom
C147 "22u" C0603 30.4,55.9 r90 bottom
C148 "22u" C0603 22,51.3 r180 bottom
C149 "220n" C0201 27.5,44.1 r90 bottom
C150 "220n" C0201 22.7,44.1 r270 bottom
C151 "22u" C0603 20.9,42.5 r180 bottom
C152 "220n" C0201 25.3,52.9 r90 bottom
C153 "220n" C0402 16.6,57.2 r180 bottom
C154 "220n" C0201 25.3,51.5 r270 bottom
C155 "220n" C0201 32,53.7 r0 bottom
C156 "22u" C0603 32.9,56.1 r0 bottom
C157 "220n" C0201 35.2,44.4 r0 bottom
C158 "220n" C0201 34.4,46 r0 bottom
C159 "220n" C0201 34.4,47 r0 bottom
C160 "220n" C0201 34.4,47.6 r0 bottom
C161 "220n" C0201 34.5,50.5 r90 bottom
C162 "220n" C0201 33.9,50.3 r90 bottom
C163 "220n" C0201 32,43.8 r0 bottom
C164 "220n" C0201 23.865,49.7 r270 bottom
C165 "220n" C0201 25.3,50.3 r90 bottom
C166 "220n" C0201 27.2,53.7 r180 bottom
C167 "220n" C0201 34.9,52.9 r90 bottom
C168 "220n" C0201 33.6,52.4 r0 bottom
C169 "220n" C0201 33.9,51.5 r90 bottom
C170 "220n" C0201 31.7,52.7 r270 bottom
C171 "220n" C0201 32.3,52.7 r270 bottom
C172 "22u" C0603_small 35.1,48.9 r0 bottom
C173 "22u" C0603_small 33.6,54.1 r90 bottom
C174 "220n" C0201 26.9,44.1 r90 bottom
C175 "22pF" C0402 20.8,71.1 r90 top
C176 "22pF" C0402 20.8,68.9 r270 top
C177 "22pF" C0402 9.2,10.7 r270 bottom
C178 "22pF" C0402 6.7,10.1 r270 bottom
C179 "22pF" C0402 6.7,14.3 r90 bottom
C180 "10u" C0603 13.1,65.5 r0 bottom
C181 "100n" C0402 10.4,69.6 r180 bottom
C182 "10n" C0402 12.7,68.8 r0 bottom
C183 "10n" C0402 12.7,66.8 r0 bottom
C184 "10n" C0402 12.5,64.1 r0 bottom
C185 "10n" C0402 14.5,64.1 r0 bottom
C186 "10u" C0603 15.3,72 r180 bottom
C187 "100n" C0402 15.5,70 r270 bottom
C188 "10n" C0402 14.5,70 r270 bottom
C189 "10n" C0402 16.5,70 r270 bottom
C190 "100n" C0402 12.3,70.5 r270 bottom
C191 "10u" C0603 21.8,69.6 r0 bottom
C192 "100n" C0402 20.3,67.8 r270 bottom
C193 "10n" C0402 18.6,67.2 r180 bottom
C194 "10u" C0603 14.9,60.4 r270 bottom
C195 "100n" C0402 10.4,68.4 r180 bottom
C196 "10n" C0402 18.6,66.1 r180 bottom
C197 "10n" C0402 17.1,64.1 r90 bottom
C198 "10n" C0402 12.7,67.8 r0 bottom
C199 "10u" C0603 21.8,71.1 r0 bottom
C200 "10n" C0402 13.4,70.5 r270 bottom
C201 "10n" C0402 18.6,68.3 r180 bottom
C202 "10n" C0402 17.7,70 r270 bottom
C203 "220n" C0201 47.8,72.1 r180 top
C204 "220n" C0201 55,72.1 r0 top
C205 "220n" C0201 56.8,72.1 r0 top
C206 "100n" C0201 50.9,23.3 r90 top
C207 "100n" C0402 25.8,37.2 r180 top
C208 "4u7" C0402 33.5,44.4 r90 bottom
C209 "4u7" C0402 18.4,51.8 r270 bottom
C210 "22pF" C0402 9.2,12.7 r270 bottom
C211 "18p" C0201 20.3,44.3 r270 bottom
C212 "18p" C0201 20.8,45.2 r0 bottom
C213 "100n" C0402 29.3,76.9 r90 top
C214 "100n" C0402 29.3,79.1 r270 top
C215 "100n" C0402 28.9,83 r180 top
C216 "100n" C0402 40.4,87.7 r180 bottom
C217 "100n" C0402 41,83 r0 top
C218 "100n" C0402 54.4,26 r0 bottom
C219 "100n" C0402 21.8,19.1 r180 top
C220 "10n" C0402 21.8,18.1 r180 top
C221 "100n" C0402 15.9,23.5 r270 top
C222 "10n" C0402 16.9,23.5 r270 top
C223 "18p" C0402 23.5,20.5 r270 bottom
C224 "18p" C0402 23.4,18.2 r90 bottom
C225 "10u" C0603 6.8,59.6 r0 bottom
C226 "100n" C0402 6.7,60.9 r0 bottom
C227 "10u" C0603 31.7,13.7 r270 top
C228 "100n" C0402 33,13.2 r270 top
C229 "100n" C0201 58.2,32.7 r270 top
C230 "100n" C0402 11,3.3 r180 bottom
C231 "10u" C0603 24.2,6.9 r0 top
C232 "100n" C0402 21.5,7.2 r180 top
C233 "100u / 10V" C2312 46.7,90.5 r90 bottom
C234 "100u / 10V" C2312 46.7,90.5 r90 top
C235 "100n" C0402 52.7,87.6 r180 bottom
C236 "100n" C0402 57.7,75.8 r0 bottom
C237 "1u" C0402 66.1,82.9 r90 top
C238 "100u / 10V" C2312 7.4,72.1 r90 bottom
C239 "10u" C0603 12.9,79.5 r90 bottom
C240 "10u" C0603 18.8,80.7 r90 bottom
C241 "560pF" C0402 18.4,78.6 r180 bottom
C242 "18p" C0402 64.3,76.5 r0 bottom
C243 "100n" C0402 64.6,70.6 r90 bottom
C244 "4u7" C0402 28.1,38 r0 bottom
C245 "4u7" C0402 63.4,70.6 r270 bottom
C246 "4u7" C0402 29.1,39.1 r180 bottom
C247 "4u7" C0402 31,37.4 r0 bottom
C248 "10n" C0402 16.1,64.1 r90 bottom
C249 "10n" C0402 18.6,65 r180 bottom
C250 "100n" C0402 68,70.8 r0 bottom
C251 "4u7" C0402 68,72 r180 bottom
C252 "100n" C0402 44.1,82.9 r0 bottom
C253 "1u" C0402 59.8,78.1 r180 bottom
C254 "1u" C0402 63.7,68.7 r0 top
C255 "100n" C0402 58.7,74.6 r0 bottom
C256 "100n" C0402 62.2,70.6 r90 bottom
C257 "330u" C2917 53.4,19.7 r180 top locked
C258 "330u" C2917 42,19.7 r180 top locked
C259 "100n" C0402 56.6,26.2 r90 bottom
C260 "100n" C0402 44.9,26 r180 bottom
C261 "100n" C0402 38,26.2 r90 bottom
C262 "4u7" C0402 31.6,20.7 r180 bottom
C263 "4u7" C0402 41.1,13.375 r0 bottom
C264 "4u7" C0402 54.5,15.9 r180 top
C265 "100n" C0402 36.6,26.2 r90 bottom
C266 "100n" C0402 39.1,13.375 r180 bottom
C267 "100n" C0402 45.5,23.1 r180 top
C268 "100n" C0402 59.2,21.5 r0 top
C269 "100n" C0402 65.7,77.8 r0 bottom
C270 "100n" C0402 60.4,76.3 r270 bottom
C271 "1u" C0402 59.4,76.3 r90 bottom
C272 "100n" C0402 22.2,72.7 r0 bottom
C273 "100n" C0402 25.4,91.4 r90 bottom
C274 "100n" C0402 22.8,76.6 r90 bottom
C275 "100n" C0402 9.2,79 r270 bottom
C276 "100n" C0402 10.1,72.2 r90 bottom
C277 "100n" C0201 59.4,30.1 r270 top
C278 "10u" C0603 31.9,8.5 r270 bottom
C279 "100n" C0402 33.3,7.7 r270 bottom
C280 "10u" C0603 52.6,9.2 r0 top
C281 "100n" C0402 48.8,11 r90 top
C282 "100n" C0402 51.2,14.8 r0 bottom
C283 "100n" C0402 52.1,10.7 r180 top
C284 "100n" C0402 63.5,7.5 r90 bottom
C285 "100n" C0402 56.4,4.2 r270 bottom
C286 "270pF" C0402 62.5,9.1 r90 bottom
C287 "270pF" C0402 59.4,2 r270 bottom
C288 "100pF" C0402 61.9,6.3 r180 bottom
C289 "100pF" C0402 57.4,4.2 r270 bottom
C290 "220u, 4V" "C1206 -  TLN S CASE TANTAL" 55.6,6.4 r0 bottom
C291 "220u, 4V" "C1206 -  TLN S CASE TANTAL" 59.8,7.7 r270 bottom
C292 "100n" C0402 49.8,8.7 r180 top
C293 "1u" C0402 52.8,7.2 r270 bottom
C294 "100n" C0402 55.2,8.6 r90 bottom
C295 "270pF" C0402 57.5,10.6 r0 bottom
C296 "100n" C0402 40.5,8.4 r180 bottom
C297 "100n" C0201 58.4,28.2 r180 top
C298 "100n" C0402 11.6,49.9 r90 bottom
C299 "10u" C0603 63.1,46.2 r90 bottom
C300 "100n" C0402 63.3,43.6 r270 bottom
C301 "100n" C0402 65.5,66.4 r180 bottom
C302 "100n" C0402 68,66.3 r0 bottom
C303 "100n" C0402 63.3,66 r90 bottom
C304 "10uF / 16V" C0805 66.8,67.7 r180 top
C305 "100n" C0201 60.8,27 r90 top
C306 "100n" C0201 58.1,27.2 r90 top
C307 "100n" C0402 2.9,67 r270 top
C308 "100n" C0201 60.8,23.2 r180 top
C309 "100n" C0402 4,55.7 r180 bottom
C310 "100n" C0402 12.3,50.7 r0 top
C311 "100pF" C0402 3.8,45.5 r180 bottom
C312 "100pF" C0402 5.8,45.5 r0 bottom
C313 "10n" C0402 7.4,46.3 r270 bottom
C314 "100n" C0402 12.1,58.9 r90 bottom
C315 "100n" C0402 13.8,52.4 r90 top
C316 "100n" C0402 15.4,51.9 r180 top
C317 "100n" C0201 57.7,24.5 r180 top
C318 "100n" C0201 54.6,23.9 r90 top
C319 "100n" C0201 50.6,24.9 r180 top
C320 "100n" C0201 53.9,23.9 r90 top
C321 "22u" C0603 62.2,30.1 r90 top
C322 "100n" C0201 50.2,24.3 r180 top
C323 "100n" C0201 42.1,46.7 r270 top
C324 "100n" C0402 59.8,34 r0 bottom
C325 "100n" C0402 66.7,13 r90 bottom
C326 "1u" C0402 26.8,85.4 r180 top
C327 "2p2" C0201 41,50.5 r270 top
C328 "2p2" C0201 41.3,49.3 r0 top
C329 "100n" C0402 65.3,8.4 r180 top
C330 "1u" C0402 23.5,29 r0 bottom
C331 "2u2" C0402 23.4,30.2 r0 bottom
C332 "1u" C0402 24.2,23.3 r0 bottom
C333 "4u7" C0402 24,27.8 r0 bottom
C334 "2u2" C0402 25.6,24.6 r0 bottom
C335 "1u" C0402 29.5,24.1 r90 bottom
C336 "4u7" C0402 24.6,22.3 r0 bottom
C337 "2u2" C0402 28.1,21.8 r270 bottom
C338 "2u2" C0402 29.6,20.7 r180 bottom
C339 "1u" C0402 24,18.9 r180 top
C340 "100n" C0402 24,21.1 r180 top
C341 "100n" C0402 29.6,21.9 r180 bottom
C342 "100n" C0402 22.2,20.6 r270 top
C343 "470nF" C0402 31.6,21.8 r180 bottom
C344 "4u7" C0402 27.4,30 r0 bottom
C345 "100n" C0402 26.8,28.3 r270 bottom
C346 "100n" C0402 27.8,28.3 r270 bottom
C347 "4u7" C0402 28.8,28.3 r270 bottom
C348 "4u7" C0402 26.6,22.3 r180 bottom
C349 "100n" C0402 28.5,24.1 r90 bottom
C350 "100n" C0402 27.5,24.1 r90 bottom
C351 "4u7" C0402 27.6,25.9 r0 bottom
C352 "22u" C0603 32.9,33.4 r270 top
C353 "22u" C0603 30.4,35.1 r0 top
C354 "22u" C0603 31.3,32.8 r270 top
C355 "22u" C0603 29.7,32.8 r270 top
C356 "22u" C0603 32.2,19.7 r90 top
C357 "22u" C0603 30.6,19.7 r90 top
C358 "22u" C0603 32.2,16.7 r270 top
C359 "22u" C0603 30.6,16.7 r270 top
C360 "22u" C0603 21.6,33.3 r180 top
C361 "22u" C0603 21.6,34.7 r180 top
C362 "22u" C0603 18.6,29.4 r180 top
C363 "22u" C0603 18.6,30.8 r180 top
C364 "22u" C0603 18.1,23.3 r270 top
C365 "22u" C0603 19.5,23.3 r270 top
C366 "22u / 10V" C0603 34.4,29.6 r180 top
C367 "10uF / 16V" C0805 39.9,23.6 r0 top
C368 "100n" C0402 37.6,24.2 r90 top
C369 "4u7" C0402 25.4,30 r180 bottom
C370 "100n" C0402 25.7,28.3 r270 bottom
C371 "100n" C0402 25.6,25.7 r0 bottom
C372 "4u7" C0402 23.4,24.9 r180 bottom
C373 "4u7" C0402 23.4,26 r180 bottom
C374 "100n" C0402 25.6,26.8 r0 bottom
C375 "1u" C0402 29.7,25.9 r180 bottom
C376 "10uF / 16V" C0805 34.1,26.1 r0 bottom
C377 "1u" C0402 31.2,27 r180 bottom
C378 "220n" C0402 30.3,28.2 r180 bottom
C379 "1u" C0402 31.6,25.5 r270 bottom
C380 "100n" C0402 30.3,29.4 r180 bottom
C381 "22u" C0603 30.3,16.7 r270 bottom
C382 "100n" C0402 2.7,31.4 r90 bottom
C383 "100n" C0402 50.7,28.4 r270 bottom
C384 "100n" C0402 29.4,69.8 r90 top
C385 "100n" C0402 21,21.8 r90 top
C386 "100n" C0402 12.2,37.2 r180 top
C387 "4u7" C0402 63.6,18.2 r270 bottom
C388 "100n" C0402 58.9,14.6 r180 top
C389 "100n" C0402 62.5,14 r270 top
C390 "220n" C0402 63.6,17.1 r90 top
C391 "4u7" C0402 60.9,14.5 r180 top
C392 "100n" C0402 58.2,49.9 r270 top
C393 "100n" C0402 58.2,47.7 r270 top
C394 "1u" C0402 65.7,13 r90 bottom
C395 "100n" C0402 13.3,24 r180 bottom
C396 "10n" C0402 26.8,86.4 r0 top
C397 "4u7" C0402 1.8,55.7 r180 bottom
C398 "100n" C0402 63.6,15.1 r270 top
C399 "100n" C0402 61.6,19.5 r0 top
C400 "1u" C0402 39.4,30.5 r90 bottom
C401 "100n" C0402 40.6,30.5 r90 bottom
C402 "100n" C0402 42.1,30.4 r0 bottom
C403 "100n" C0402 40,28.8 r180 top
C404 "10n" C0402 36.5,31 r90 top
C405 "100n" C0402 62.4,23.9 r180 bottom
C406 "22u" C0603 14,31.6 r180 top
C407 "22u" C0603 16.3,31.9 r90 top
C408 "22u" C0603 24.5,32.9 r0 bottom
C409 "22u" C0603 24.5,34.5 r0 bottom
C410 "22pF" C0402 14.6,35.4 r0 top
C411 "220pF" C0402 14.4,35.7 r180 bottom
C412 "100n" C0402 5.7,42.6 r270 bottom
C413 "100n" C0402 1.3,40.8 r270 bottom
C414 "100n" C0402 37.6,81.1 r180 bottom
C415 "18p" C0402 61.4,75 r270 bottom
C416 "100n" C0402 64.9,86.3 r90 top
C417 "100n" C0402 28.2,69.8 r270 top
C418 "100n" C0402 27,69.8 r270 top
C419 "10u" C0603 14,55 r0 bottom
C420 "100n" C0402 10.1,66.9 r90 bottom
C421 "10uF / 16V" C0805 58.9,85 r270 bottom
C422 "100n" C0402 64.8,82.3 r90 bottom
C423 "100n" C0402 12.3,43.6 r180 top
C424 "22u" C0603 21.6,31.9 r180 top
C425 "22u" C0603 18.5,32.4 r180 top
C426 "22u" C0603 19.5,26.7 r90 top
C427 "22u" C0603 15,86.8 r270 bottom
C428 "22u" C0603 16.6,86.8 r270 bottom
C429 "22u" C0603 21.4,87 r270 bottom
C430 "22u" C0603 19.8,87 r270 bottom
C431 "22u" C0603 18.2,87 r270 bottom
C432 "22pF" C0402 14,93.3 r90 bottom
C433 "220pF" C0402 11.6,93.3 r270 bottom
C434 "22u / 10V" C0603 34.4,31.1 r180 top
C435 "100n" C0402 31.2,24 r180 bottom
C436 "2u2" C0402 31.2,23 r180 bottom
C437 "1u" C0402 24,20 r180 top
CR1 "Mini PCIe Card" "MINI_PCIE_FULL CARD" 32,19.5 r90 bottom
CR2 "Micro SD Card" MICRO_SD_CARD 42.9,13.25 r0 top
CR3 "Micro SIM Card" MICRO_SIM_CARD 44.5,30.8 r0 bottom
D1 "Red" LED_0603 2.1,84.2 r180 top
D2 "Red" LED_0603 2.1,82 r180 top
D3 "Red" LED_0603 2.1,79.8 r180 top
D4 "PGB1010603MR" C0603 66,79.9 r270 bottom
D5 "Red" LED_0603 2.1,75.4 r180 top
D6 "Red" LED_0603 2.1,73.2 r180 top
D7 "Red" LED_0603 2.1,71 r180 top
D8 "PGB1010603MR" C0603 66,75.5 r270 bottom
D9 "S8MC-13" SMC 23.7,14.4 r180 top locked
D10 "RB751V-40-TP" SOD323 24.8,67.5 r180 top
D11 "Green" LED_0603 32.2,11.3 r0 top
D12 "Orange" LED_0603 68.8,70.5 r270 top
D13 "BAT54HT1G" SOD323 40.8,74.1 r270 top
D14 "Orange" LED_0603 51,1.9 r270 top
D15 "BZA956A,115" SOT665 51.3,26.5 r180 bottom
D16 "BGX50AE6327" SOT143 25.9,8.9 r0 bottom
D17 "BGX50AE6327" SOT143 54.1,85.2 r270 bottom
D18 "MBR140SFT1G" SOD-123FL 35.1,27.7 r180 top
D19 "PGB1010603MR" C0603 27,6.9 r0 top
D20 "BGX50AE6327" SOT143 54.5,76.8 r90 bottom
D21 "Orange" LED_0603 31.6,1.9 r270 top
D22 "Green" LED_0603 3.8,8.3 r180 top
D23 "BGX50AE6327" SOT143 9.1,67.6 r180 top
D24 "Orange" LED_0603 18.5,1.9 r270 top
D25 "Green" LED_0603 32.2,9.4 r0 top
D26 "Green" LED_0603 32.2,7.5 r0 top
D27 "RB751V-40-TP" SOD323 9.3,2.6 r90 bottom
D28 "RB751V-40-TP" SOD323 29.7,32.1 r270 bottom
D29 "RB751V-40-TP" SOD323 6.3,24.7 r180 bottom
D30 "MBR140SFT1G" SOD-123FL 56.3,88 r180 bottom
D31 "PGB1010603MR" C0603 66,72.4 r270 bottom
D32 "PGB1010603MR" C0603 65.4,86.7 r180 bottom
D33 "Red" LED_0603 2.1,77.6 r180 top
D34 "Red" LED_0603 2.1,68.8 r180 top
D35 "RB751V-40-TP" SOD323 19.2,59.9 r0 bottom
D36 "RB751V-40-TP" SOD323 23.9,15.2 r0 bottom
D37 "BZA956A,115" SOT665 7.4,12.2 r0 bottom
D38 "MBR140SFT1G" SOD-123FL 59.2,88 r0 bottom
D39 "RB751V-40-TP" SOD323 1.5,24.5 r270 bottom
FB1 "220R, 2.5A" C0603 22.4,39.4 r90 bottom
FB2 "220R, 2.5A" C0603 22.8,9.9 r0 bottom
FB3 "BLM18KG101TN1D" C0603 12,62 r90 bottom
FB4 "BLM18KG101TN1D" C0603 18.1,72 r180 bottom
FB5 "BLM15AX601SN1D" C0402 22.2,67.8 r90 bottom
FB6 "BLM18KG101TN1D" C0603 13.4,60.4 r90 bottom
FB7 "BLM18KG101TN1D" C0603 24.8,71.9 r180 bottom
FB8 "BLM15AX300SN1D 30R / 1.1A" C0402 21.7,63.7 r180 bottom
FB9 "220R, 2.5A" C0603 54.5,14.6 r0 top
FB10 "220R, 2.5A" C0603 31,19 r180 bottom
FB11 "MPZ1608S601A 600OHM/1A" C0603 52,13.2 r0 top
FB12 "MPZ1608S601A 600OHM/1A" C0603 50.2,10.6 r90 top
FB13 "MPZ1608S601A 600OHM/1A" C0603 50.4,16.1 r180 top
FB14 "220R, 2.5A" C0603 30.4,8.5 r90 bottom
FB15 "120R, 1.3A" C0402 9.7,9.2 r0 bottom
FB16 "220R, 2.5A" C0603 6.8,58 r180 bottom
FB17 "220R, 2.5A" C0603 34.4,17.9 r0 top
FB18 "BLM15AX601SN1D" C0402 56.4,8.6 r90 bottom
FB19 "MPZ1608S601A 600OHM/1A" C0603 60.4,67.3 r90 top
FB20 "MPZ1608S601A 600OHM/1A" C0603 50.5,13.2 r0 top
FB21 "BLM15AX601SN1D" C0402 61.4,9.1 r90 bottom
FB22 "BLM15AX601SN1D" C0402 58.9,3.5 r0 bottom
FB23 "MPZ1608S601A 600OHM/1A" C0603 43.2,81.4 r180 bottom
FB24 "MPZ1608S601A 600OHM/1A" C0603 46.2,81.4 r0 bottom
FB25 "120R, 1.3A" C0402 7.7,10.1 r90 bottom
FB26 "MPZ1608S601A 600OHM/1A" C0603 51.9,16.1 r0 top
FB27 "120R, 1.3A" C0402 7.7,14.3 r270 bottom
FB28 "120R, 1.3A" C0402 11.6,15.3 r270 bottom
FB29 "BLM15AX601SN1D" C0402 25.4,16.4 r180 bottom
FB30 "BLM15AX601SN1D" C0402 23.4,16.4 r0 bottom
FB31 "220R, 2.5A" C0603 67.6,67.8 r0 bottom
FB32 "220R, 2.5A" C0603 66.1,67.8 r180 bottom
FB33 "MPZ1608S601A 600OHM/1A" C0603 62.4,19.9 r270 bottom
FB34 "220R, 2.5A" C0603 7,64.8 r270 bottom
FB35 "220R, 2.5A" C0603 7,66.3 r90 bottom
FB36 "MPZ1608S601A 600OHM/1A" C0603 38.1,27.9 r0 bottom
FB37 "220R, 2.5A" C0603 35.9,17.9 r180 top
FB38 "MPZ1608S601A 600OHM/1A" C0603 41.7,81.4 r0 bottom
FB39 "220R, 2.5A" C0603 61.5,46.2 r90 bottom
FB40 "220R, 2.5A" C0603 12.5,56.9 r180 bottom
FB41 "220R, 2.5A" C0603 61.5,44.7 r270 bottom
FB42 "220R, 2.5A" C0603 14,56.9 r0 bottom
FB43 "BLM15AX601SN1D" C0402 7.7,50.9 r270 bottom
FB44 "BLM15AX601SN1D" C0402 7.7,49.9 r90 bottom
FID1 "FID_1MM_SMALL" FID_40X52D#1 10,1 r0 top
FID2 "FID_1MM_SMALL" FID_40X52D#2 60,7 r90 top
FID3 "FID_1MM_SMALL" FID_40X52D#2 61,92 r90 top
FID4 "FID_1MM_SMALL" FID_40X52D#2 12,92 r90 top
FID5 "FID_1MM_SMALL" FID_40X52D#3 5.5,7.5 r90 bottom
FID6 "FID_1MM_SMALL" FID_40X52D#2 62,1.5 r90 bottom
FID7 "FID_1MM_SMALL" FID_40X52D#2 7.5,94 r90 bottom
FID8 "FID_1MM_SMALL" FID_40X52D#2 61,93.5 r90 bottom
J1 "ESQ-120-14-G-S" ESQ-120-14-G-S 9.62,64.1 r0 top locked
J2 "ESQ-120-14-G-D" ESQ-120-14-G-D 65.5,64.1 r180 bottom locked
J3 "HDR 1x6, 2.54mm" HDR_1X6_2.54MM 68.04,86.3 r0 top
J4 "5787617-1" USB-2A 56,82.1 r0 top locked
J5 "47151-0001" "HDMI V1.1" 36.5,88.8 r90 top locked
J6 "L829-1J1T-43" L829-1J1T-43 16.2,84.8 r0 top locked
J7 "4-1734592-0" 4-1734592-0 4,72.1 r90 bottom locked
J8 "0471554001" SATA_VERTICAL 3.2,25.7 r270 top locked
J9 "PJ-002AH" POWER_JACK_5.5_2.1MM_NS_V1.1 12.4,12.1 r180 top locked
J10 "0532610471" 0532610471 3.7,13 r180 bottom locked
J11 "USB MICRO AB" USB_MICRO_AB 24.9,2.2 r90 top locked
J12 "1-84952-5" ZIF_RA_BOTTOM_15X1MM 41.6,5.2 r180 bottom locked
J13 "693071010811" 693071010811 41,9 r180 top locked
J14 "FC68125" FC68125 57.9,12.6 r90 top locked
J15 "MM60-52B1-E1-R650" MINI_PCIE_52PIN_CARD_CON 59.5,19.5 r90 bottom locked
J16 "MM60-EZH059-B5-R650" MINI_PCIE_52PIN_CARD_LATCH 59.1,69.8 r90 bottom locked
J17 "693022010811" SIM_MICRO_HINGED 51,36.1 r180 bottom locked
JP1 "HDR 1x2" HDR_1X2_2.54MM 2.5,19.8 r90 top
JP2 "HDR 1x2" HDR_1X2_2.54MM 1.9,86.3 r90 top locked
L1 "1u / 3.9A" IHLP_118MILX144MIL 27.3,33.3 r90 top
L2 "1u / 3.9A" IHLP_118MILX144MIL 27.6,19.5 r0 top
L3 "ACM2012-900-2P-T002" ACM2012 50.4,88.9 r90 bottom
L4 "ACM2012-900-2P-T002" ACM2012 22.8,11.6 r180 bottom
L5 "ACM2012-900-2P-T002" ACM2012 51.3,76.8 r180 bottom
L6 "ACM2012-900-2P-T002" ACM2012 41.5,26.4 r90 bottom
